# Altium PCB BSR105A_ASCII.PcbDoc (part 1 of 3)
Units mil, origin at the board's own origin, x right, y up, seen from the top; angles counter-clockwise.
Board outline 4010.03 x 4016.63 mil, 6 copper layers (Top Layer, Mid-Layer 1, Mid-Layer 2, Mid-Layer 3, Mid-Layer 4, Bottom Layer), stack 61.2 mil thick; 167 components, 58 nets, 398 pads, 190 vias.
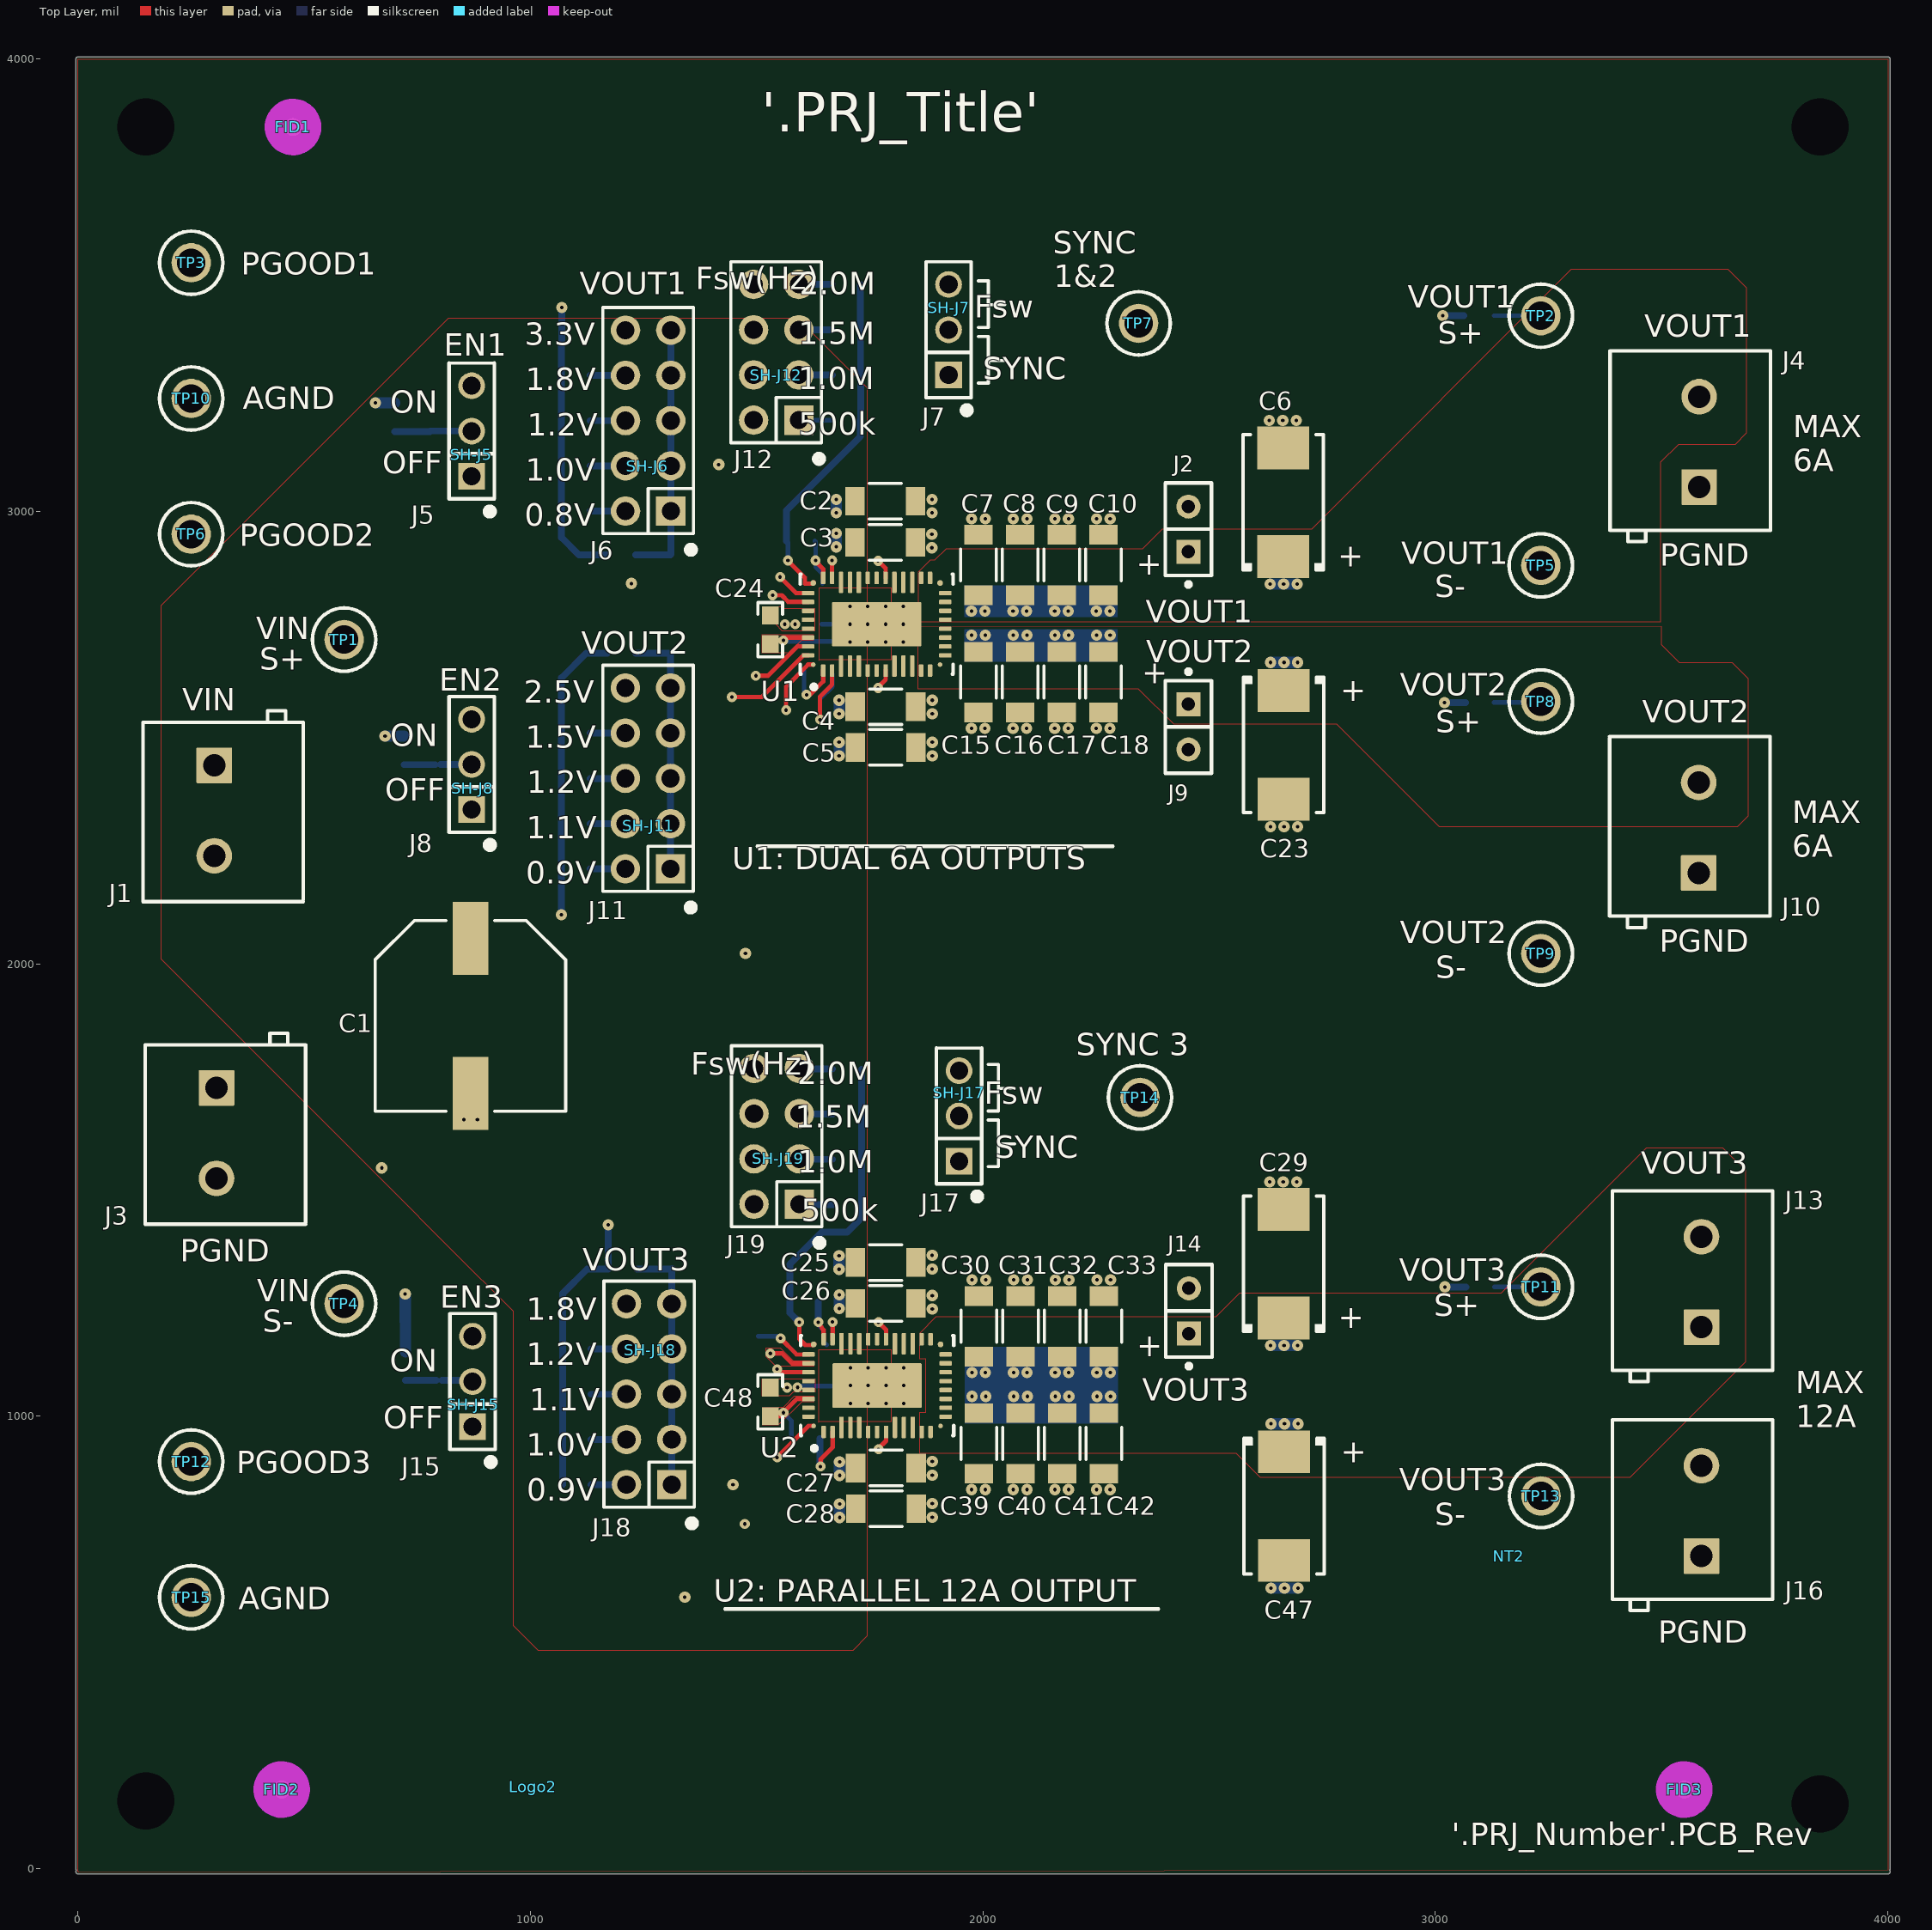
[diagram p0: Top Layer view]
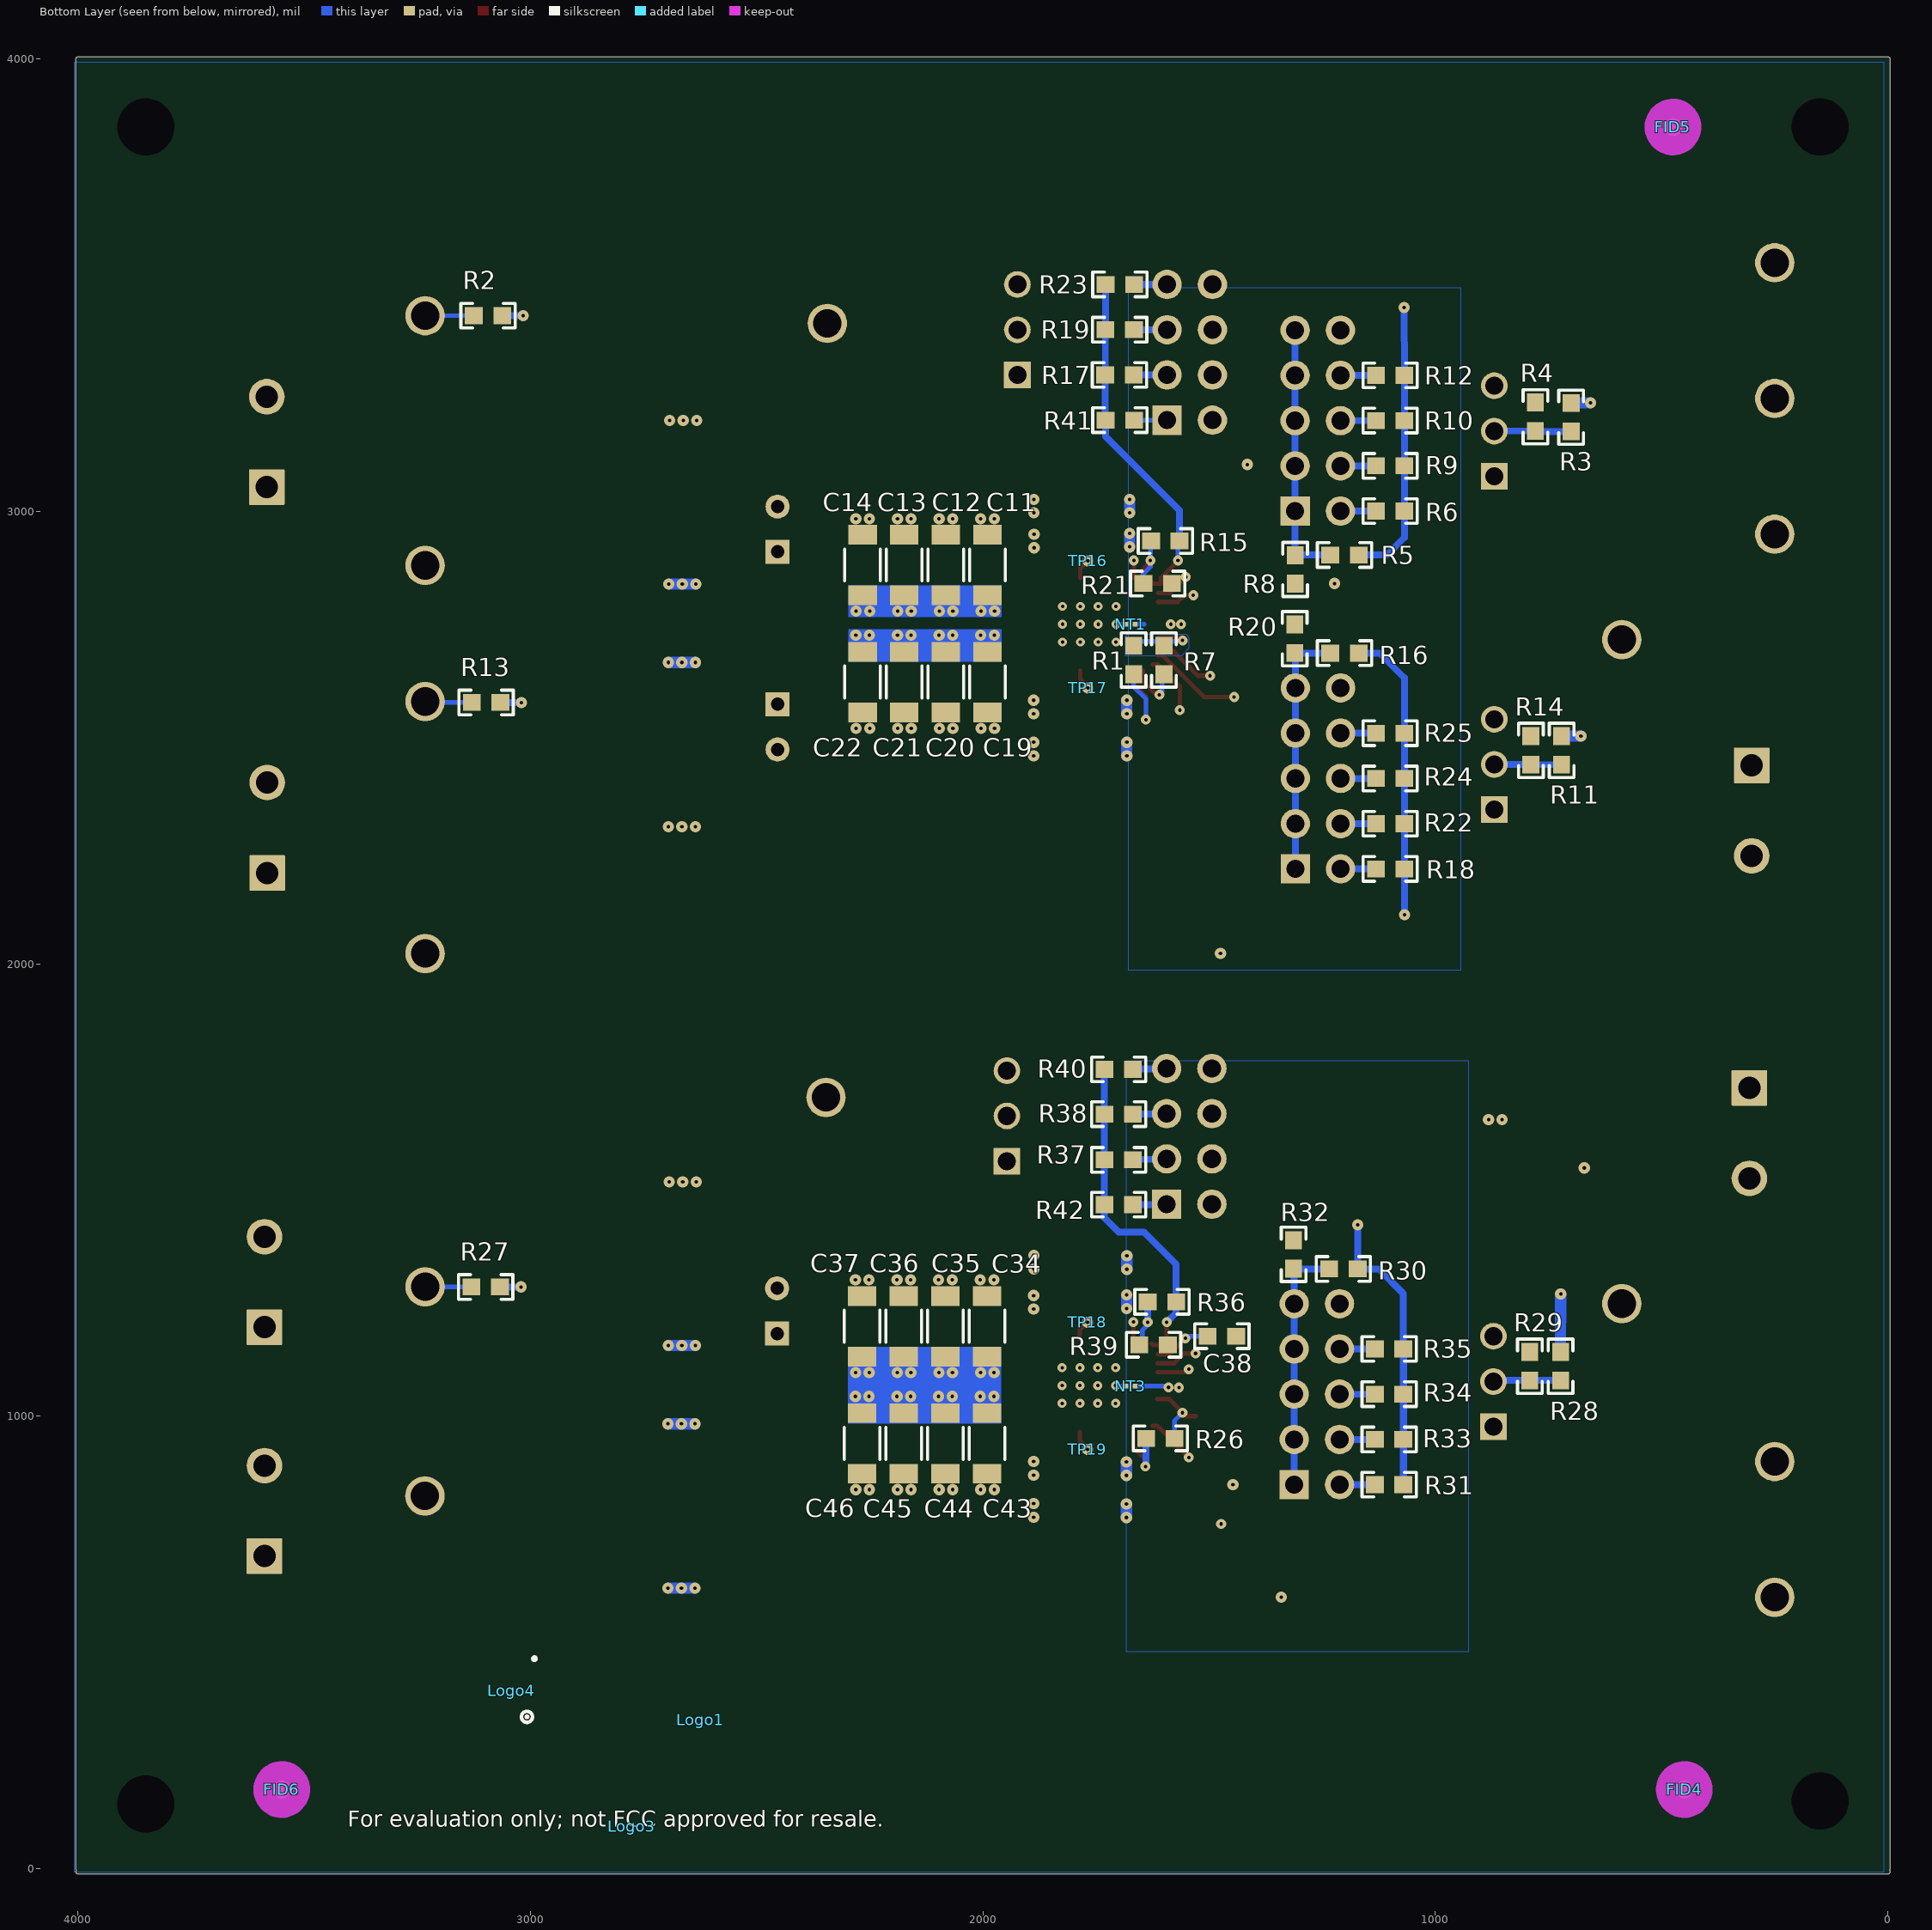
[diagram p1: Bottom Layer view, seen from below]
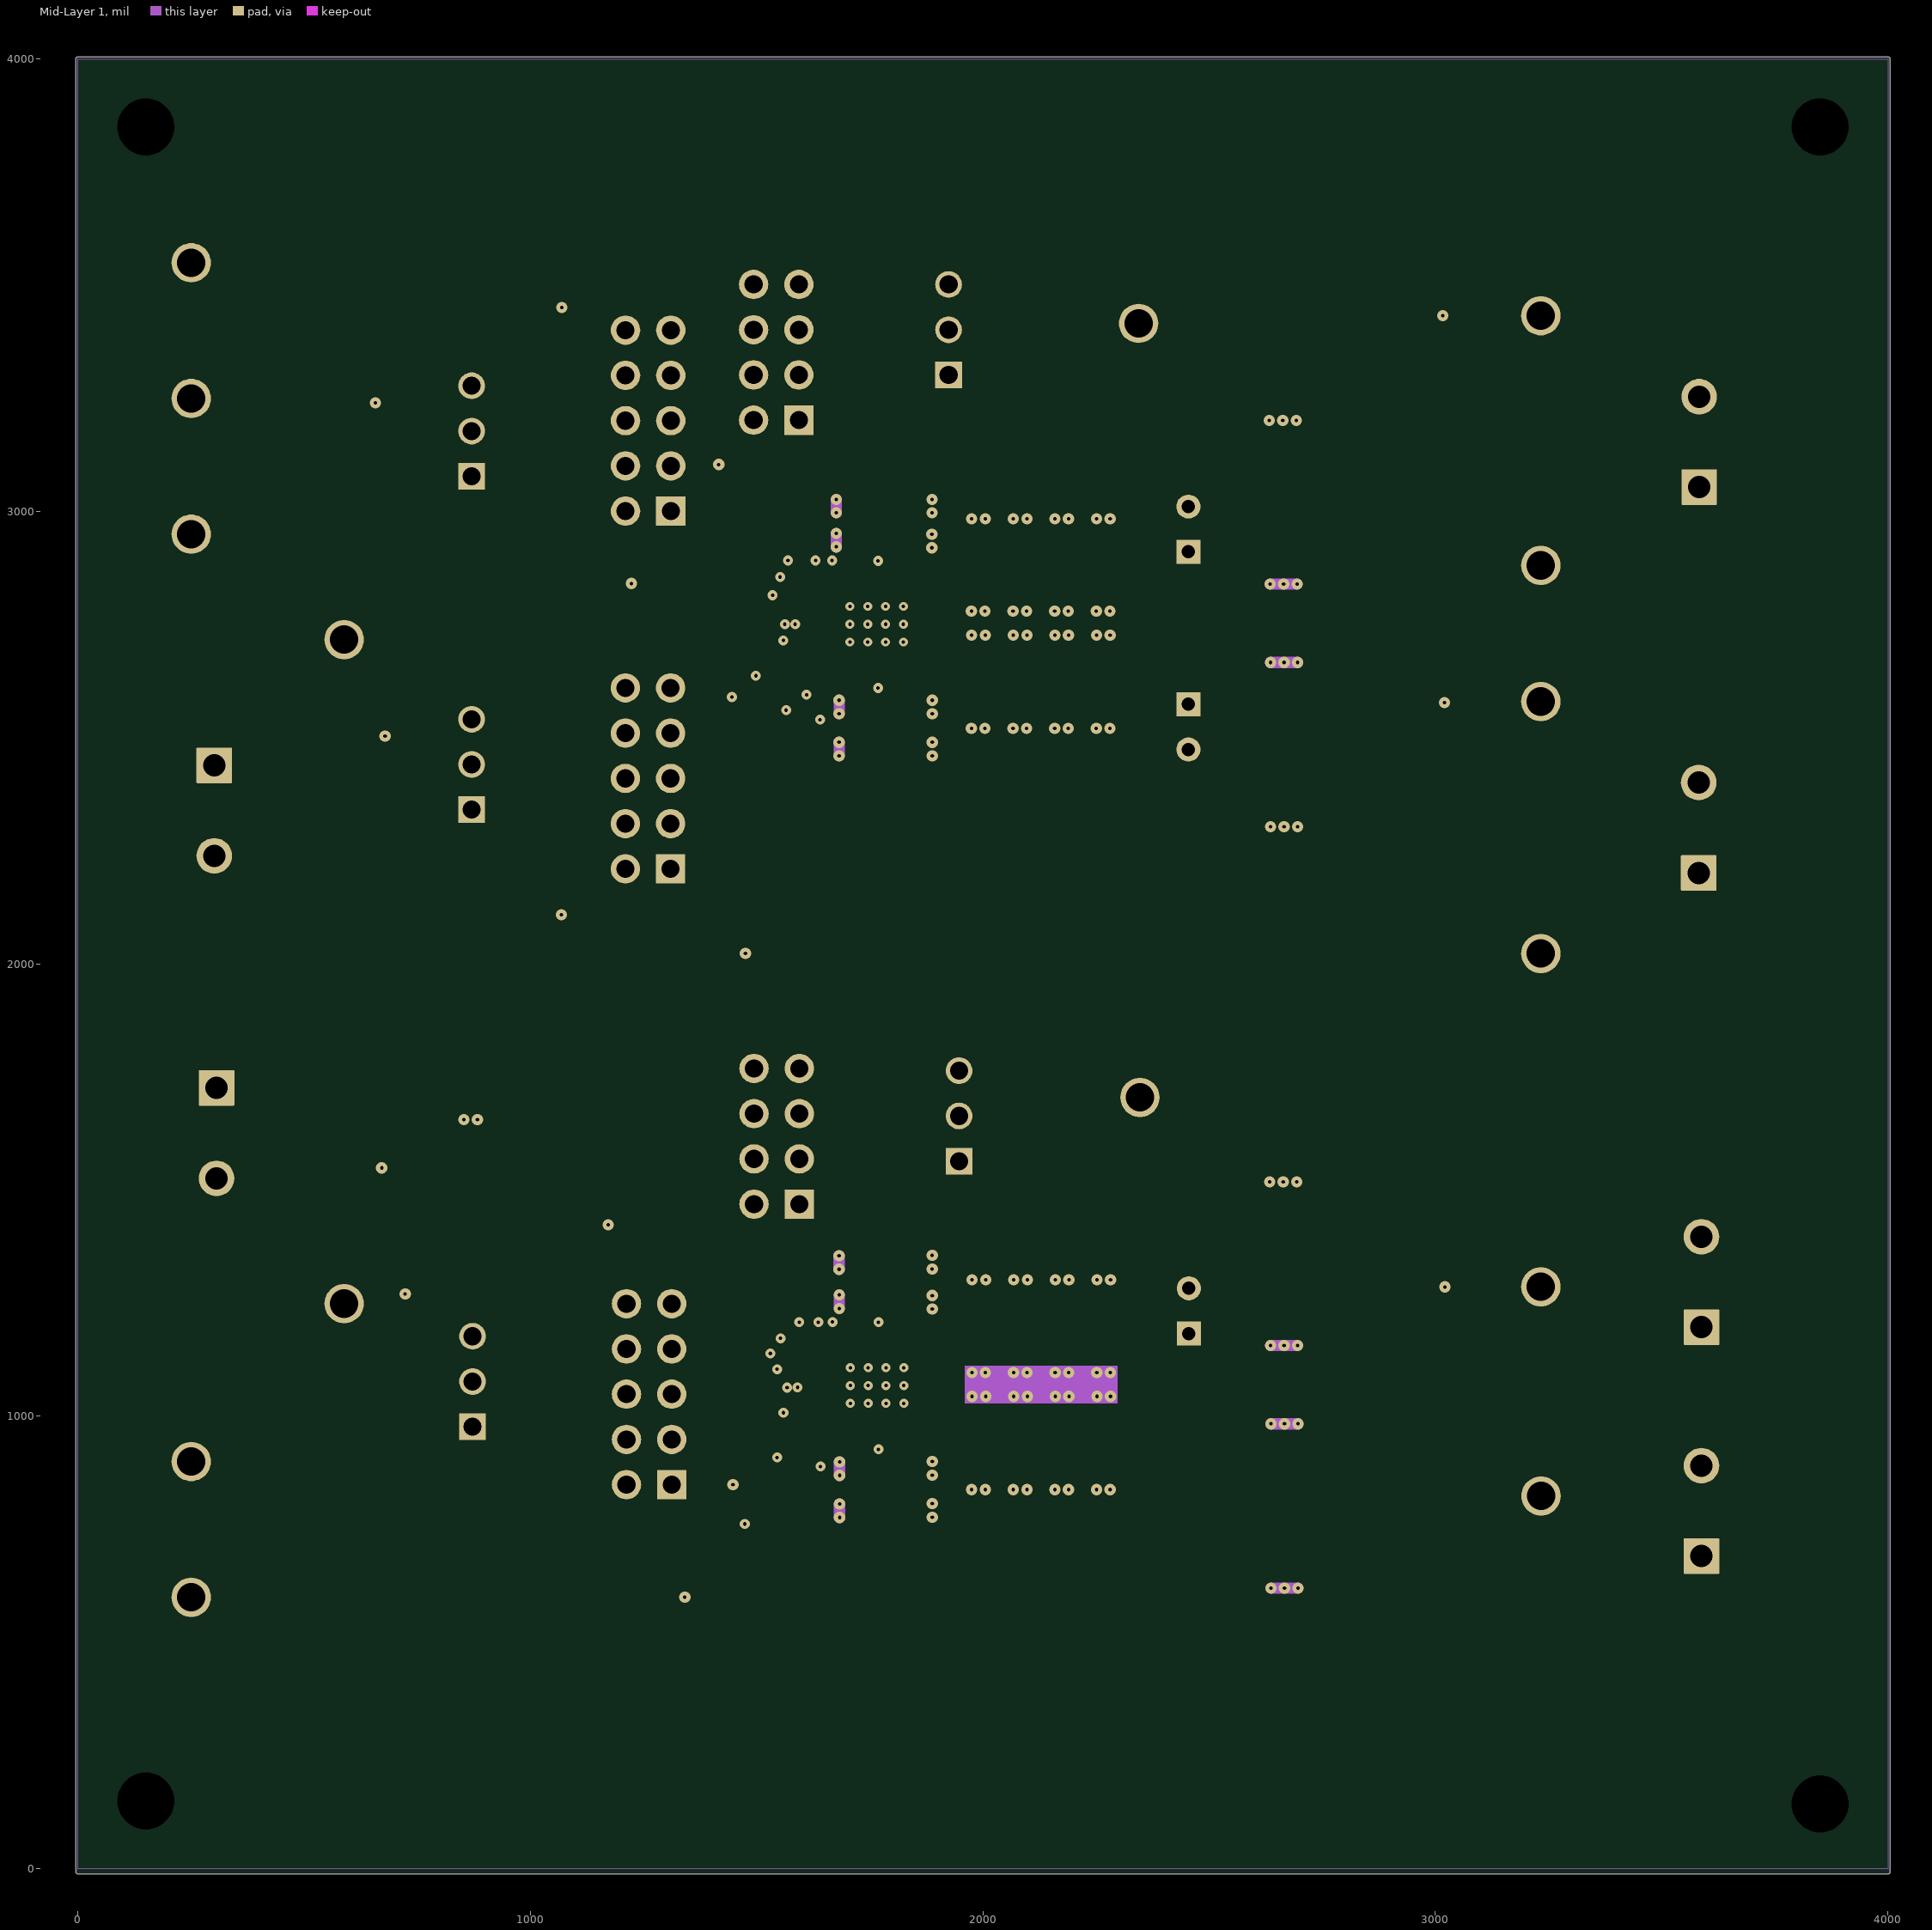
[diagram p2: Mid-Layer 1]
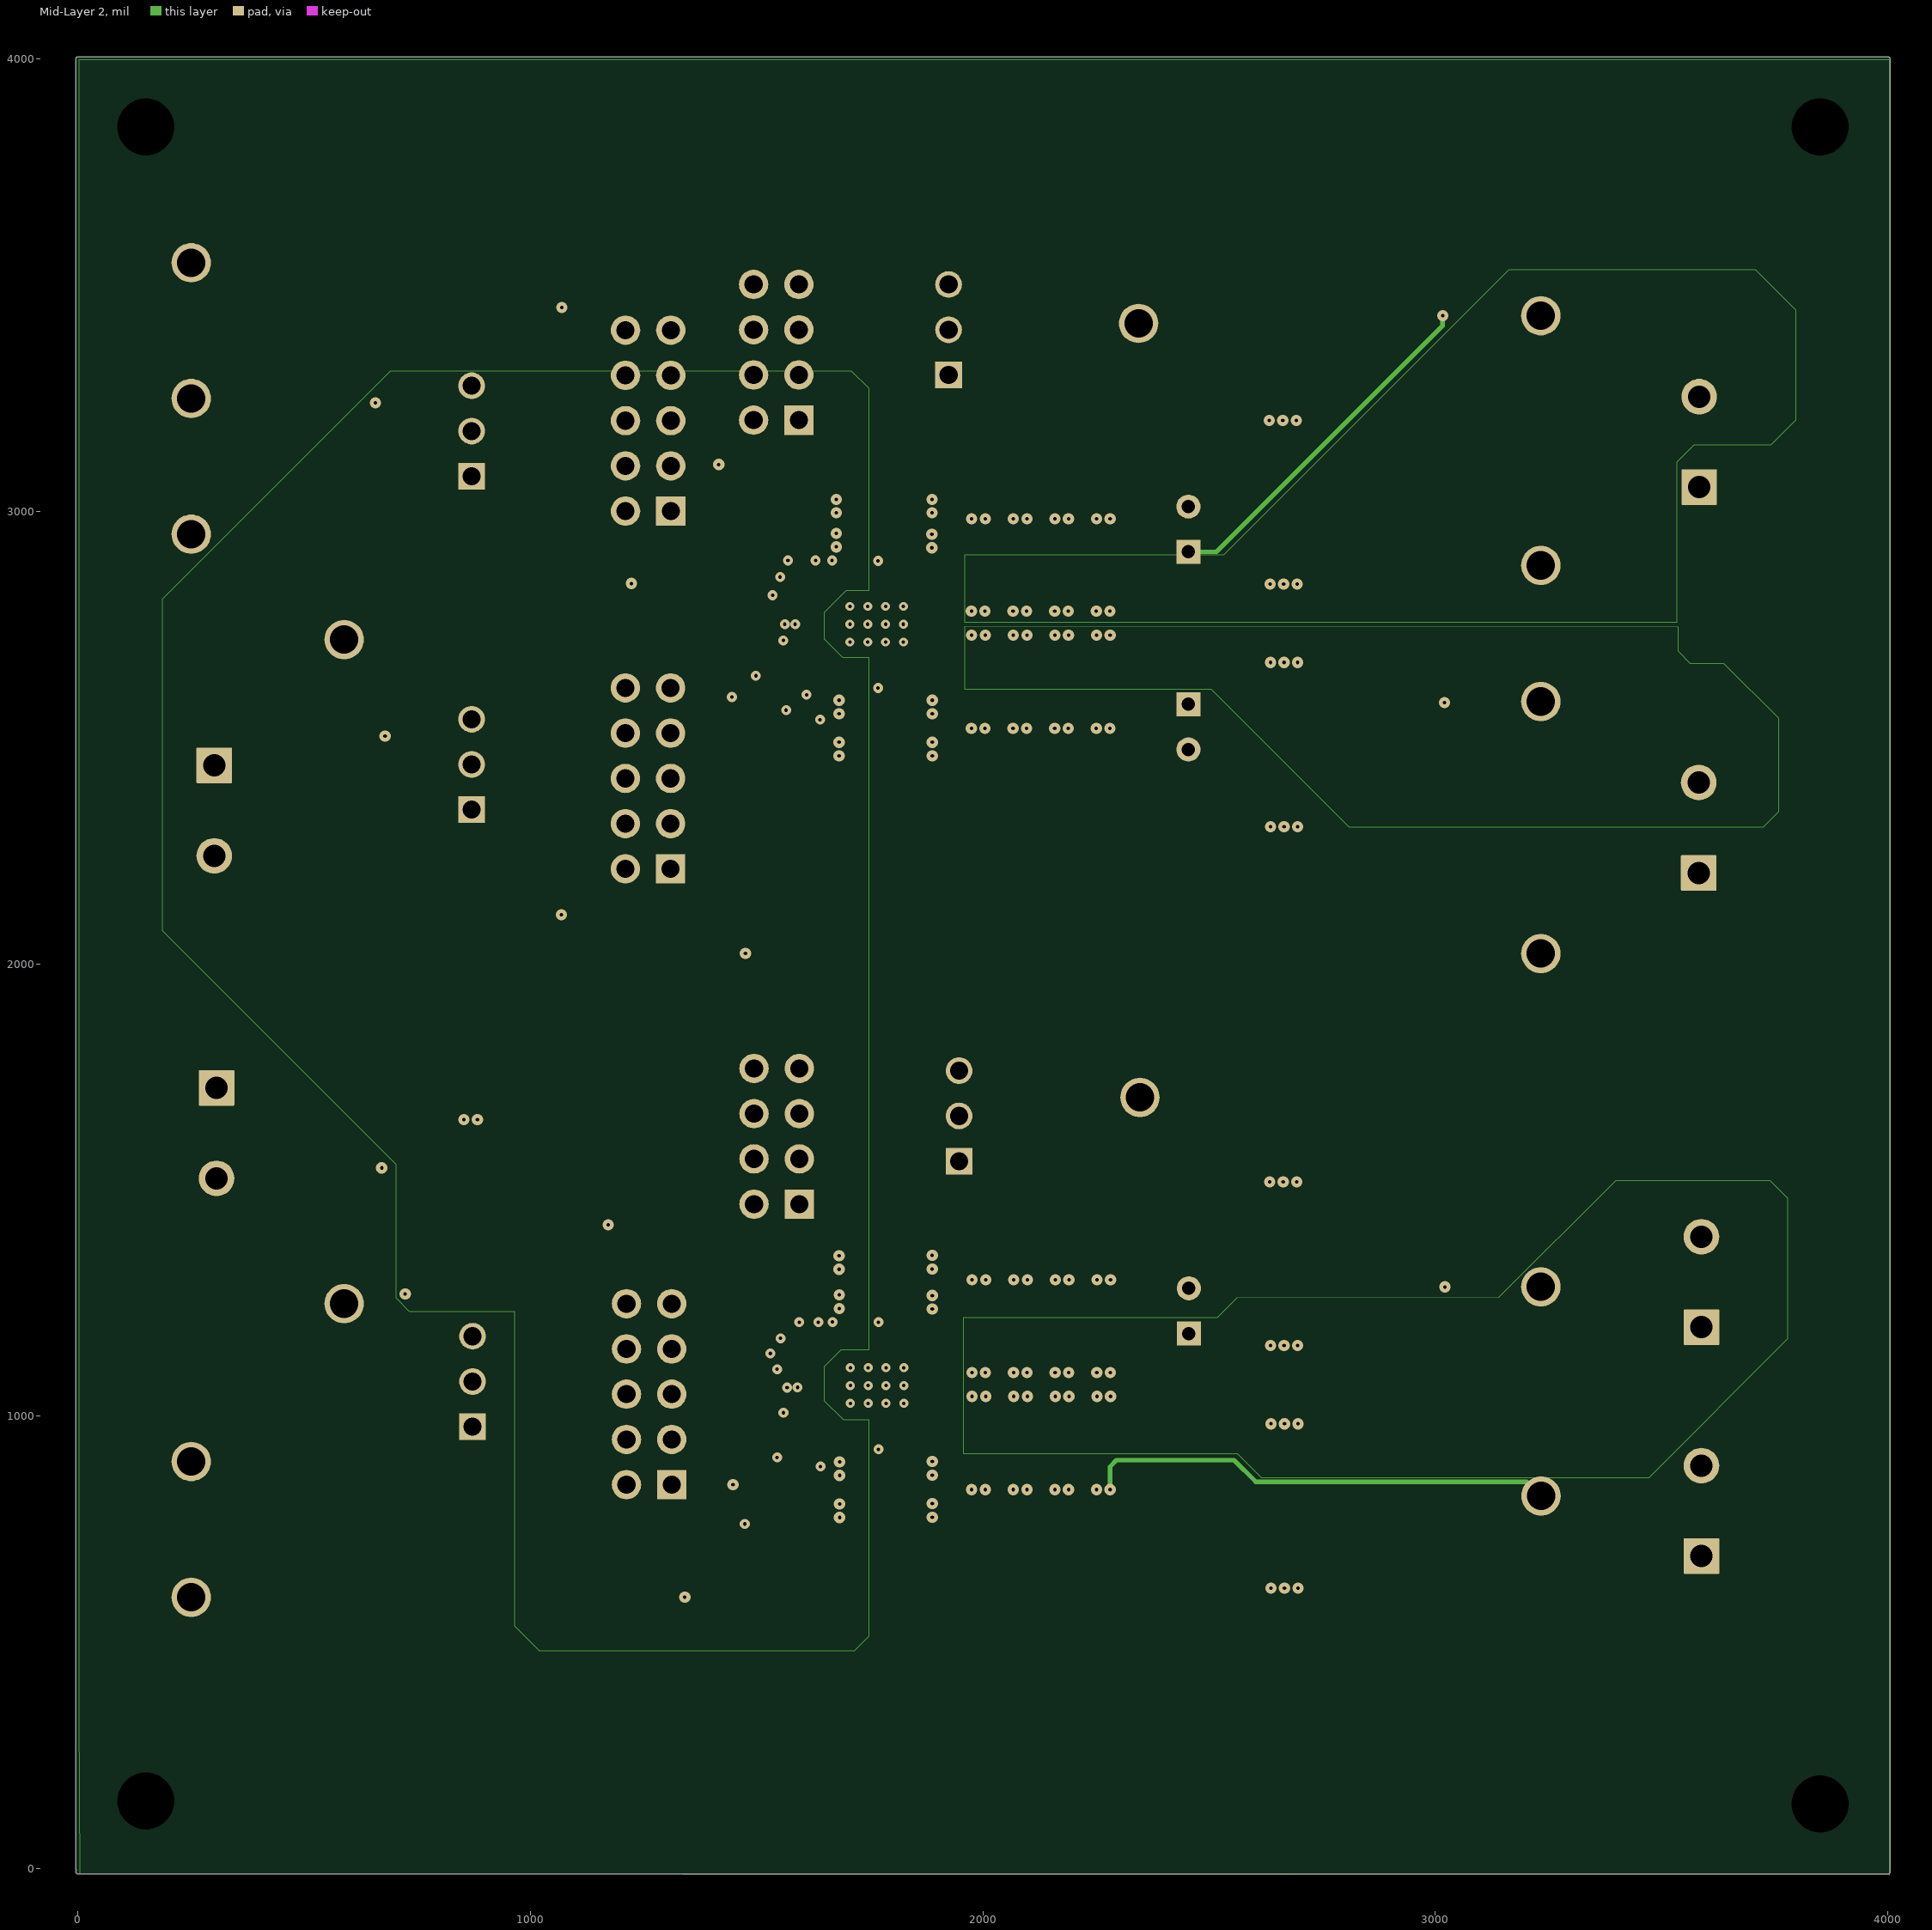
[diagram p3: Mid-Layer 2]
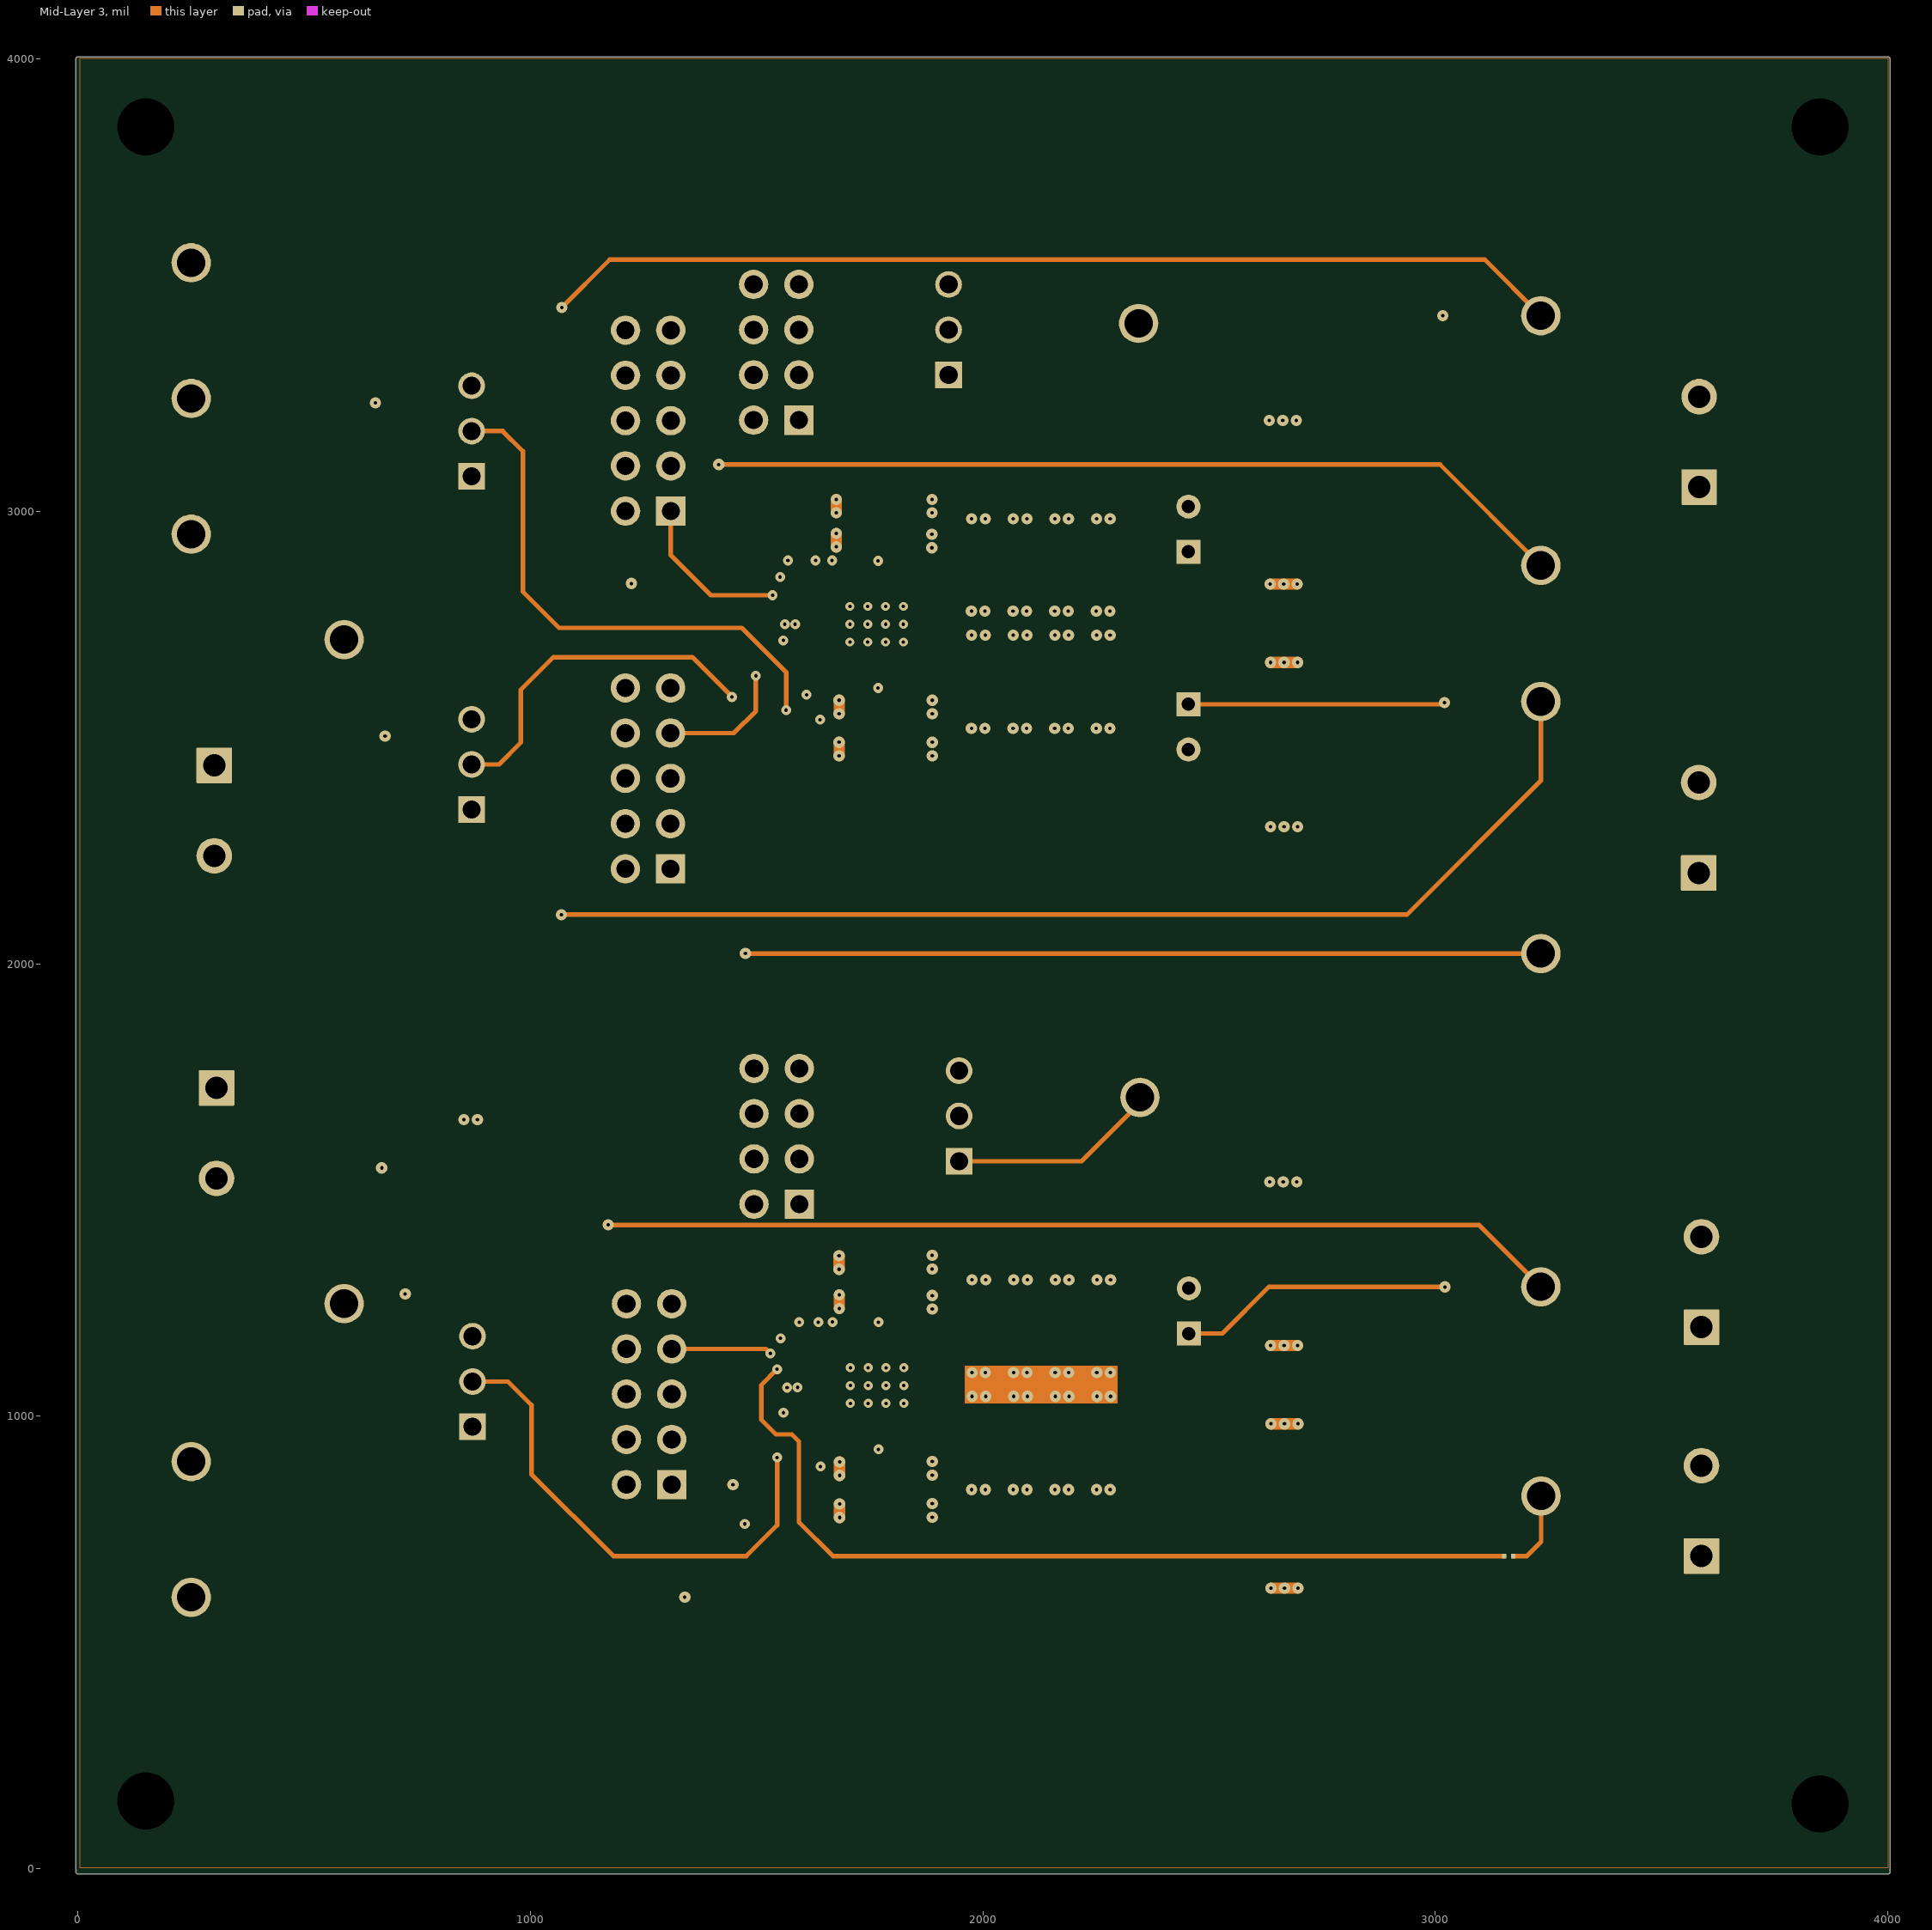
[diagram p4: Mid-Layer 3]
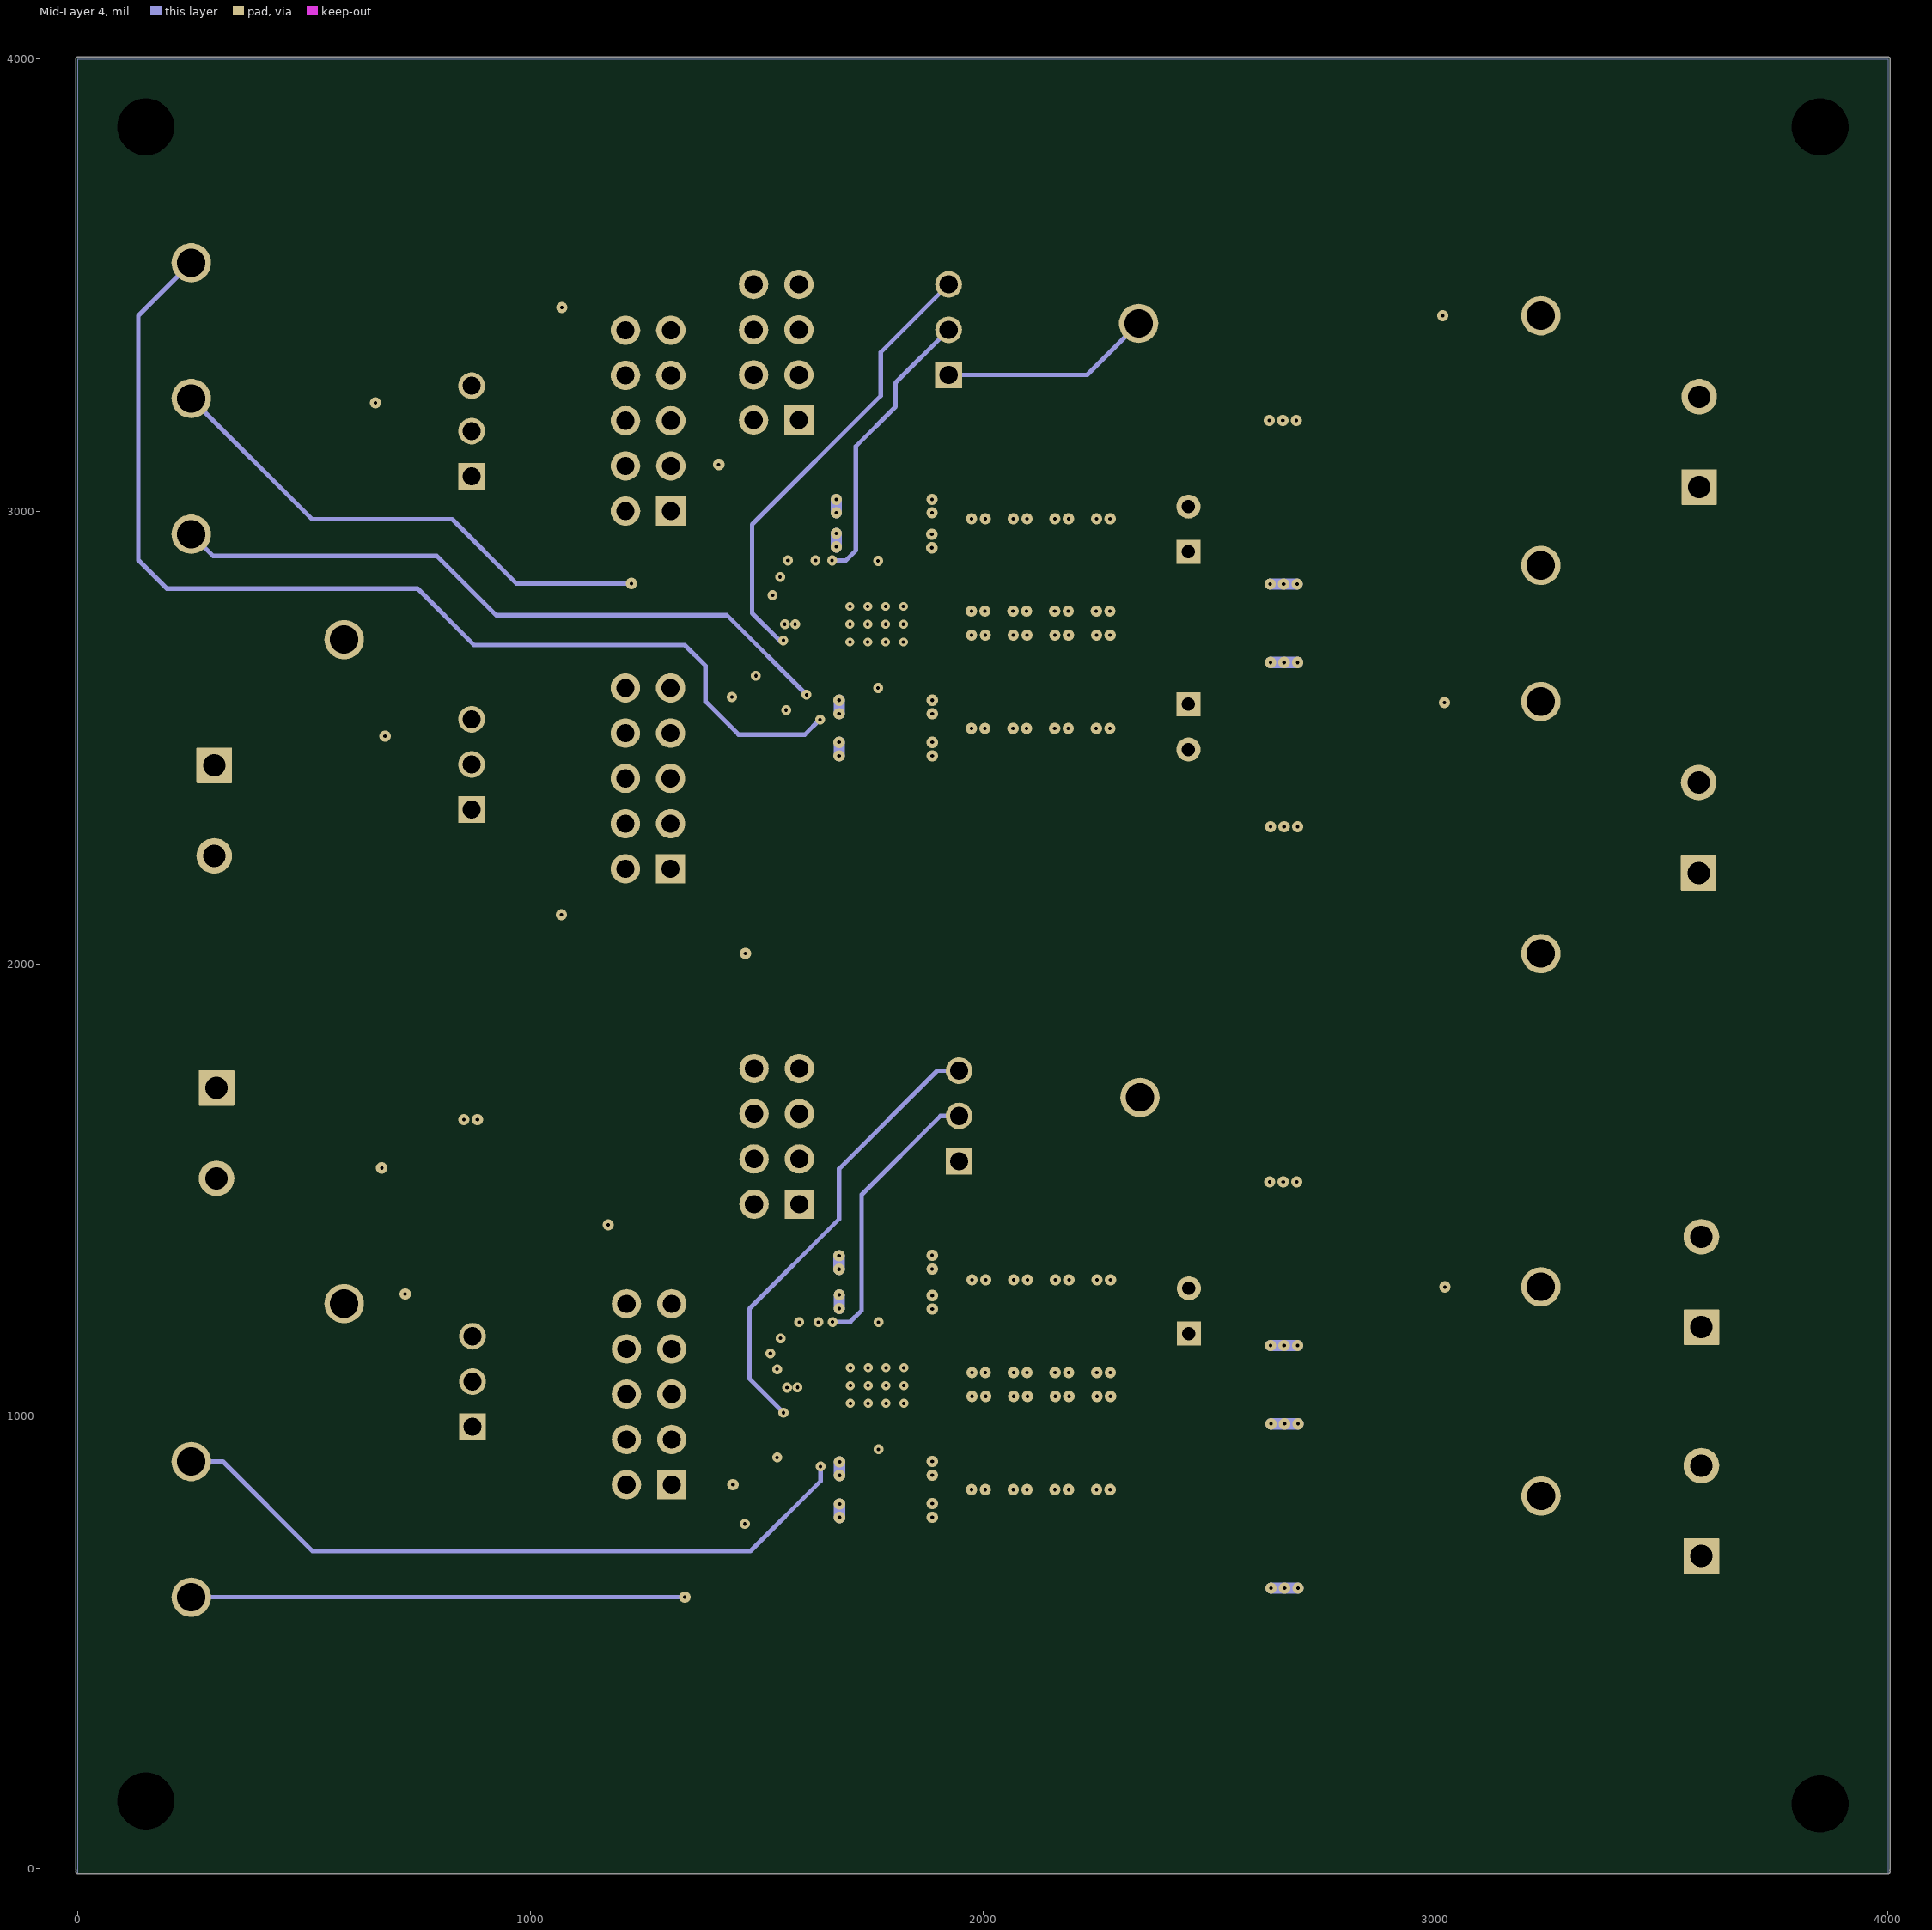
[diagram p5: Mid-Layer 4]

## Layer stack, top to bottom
Top Solder: solder mask 0.4, Solder Resist, Dk 3.5
Top Layer: signal copper 2
Dielectric1: prepreg 5, FR-4, Dk 4.2
Mid-Layer 1: signal copper 2.8
Dielectric2: core 12, FR-4, Dk 4.2
Mid-Layer 2: signal copper 2.8
Dielectric3: prepreg 12, FR-4, Dk 4.2
Mid-Layer 3: signal copper 2.8
Dielectric4: core 12, FR-4, Dk 4.2
Mid-Layer 4: signal copper 2.8
Dielectric5: prepreg 5, FR-4, Dk 4.2
Bottom Layer: signal copper 2
Bottom Solder: solder mask 0.4, Solder Resist, Dk 3.5

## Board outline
0,-11.61 cw(c0,-6.6) -3.78,-3.3 cw(c0,0) -5.01,0 -5.01,4000 cw(c0,4000) 0,4005.02 4000,4005.02 cw(c4000,4000) 4005.02,4000 4005.02,0 cw(c4000,0) 4003.78,-3.3 cw(c4000,-6.6) 4005.02,-6.6 cw(c4000,-6.6) 4000,-11.61

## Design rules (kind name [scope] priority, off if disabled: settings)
AcuteAngle [All] p0: scope1count=1 scope1_0_kind=Board scope1_0_value=Board scope2count=1 scope2_0_kind=Board scope2_0_value=Board commentlength=0 minimum=4.50000000000000E+0001
AcuteAngle [All] p1: minimum=4.50000000000000E+0001 checktracksonly=FALSE
AssemblyTestPointUsage [All] p0: scope1count=1 scope1_0_kind=Board scope1_0_value=Board scope2count=1 scope2_0_kind=Board scope2_0_value=Board commentlength=0
AssemblyTestPointUsage [All] p1: valid=2
AssemblyTestpoint [All] p0: scope1count=1 scope1_0_kind=Board scope1_0_value=Board scope2count=1 scope2_0_kind=Board scope2_0_value=Board commentlength=0
BoardOutlineClearance [All] p0 off: scope1count=1 scope1_0_kind=Board scope1_0_value=Board scope2count=1 scope2_0_kind=Board scope2_0_value=Board commentlength=173 gap=40 // Protel DXP Scope 1 Expression Was: OnCopper and not (InComponentClass('FiducialMark') or (Keepout or IsText) or  InComponentClass('Logo') or InRegion(1000,500,4000,800))
BoardOutlineClearance BoardOutlineClearance_Poly [All] p0 off: scope1count=1 scope1_0_kind=Board scope1_0_value=Board scope2count=1 scope2_0_kind=Board scope2_0_value=Board commentlength=58 gap=20 // Protel DXP Scope 1 Expression Was: OnCopper and InPoly
BoardOutlineClearance BoardOutlineClearance_MountingHoles [All] p0 off: scope1count=1 scope1_0_kind=Board scope1_0_value=Board scope2count=1 scope2_0_kind=Board scope2_0_value=Board commentlength=86 gap=40 // Protel DXP Scope 1 Expression Was: OnCopper and InComponentClass('Mounting Holes')
BoardOutlineClearance BoardOutlineClearance_MountingHoles [OnCopper and InComponentClass('Mounting Holes')] p1: gap=40 ignorepadtopadclearanceinfootprint=FALSE
BoardOutlineClearance BoardOutlineClearance_Poly [OnCopper and InPoly] p2: gap=20 ignorepadtopadclearanceinfootprint=FALSE
BoardOutlineClearance [OnCopper and not (InComponentClass('FiducialMark') or (Keepout or IsText) or  InComponentClass('Logo') or InRegion(1000,500,4000,800))] p3: gap=40 ignorepadtopadclearanceinfootprint=FALSE except(20: Poly-OutlineEdge)
Clearance Clearance_Poly [All] p0 off: scope1count=1 scope1_0_kind=Board scope1_0_value=Board scope2count=1 scope2_0_kind=Board scope2_0_value=Board commentlength=48 gap=9 // Protel DXP Scope 1 Expression Was: InPolygon
Clearance Clearance_U1-U2 [All] p0: scope1count=2 scope1_0_kind=Component scope1_0_value=U1 scope1_1_kind=Component scope1_1_value=U2 scope2count=1 scope2_0_kind=Board scope2_0_value=Board commentlength=0 gap=7
Clearance Clearance_BoardEdge [All] p0 off: scope1count=1 scope1_0_kind=Board scope1_0_value=Board scope2count=1 scope2_0_kind=Board scope2_0_value=Board commentlength=48 gap=22 // Protel DXP Scope 2 Expression Was: IsKeepOut
Clearance Clearance_BoardEdge_Poly [All] p0 off: scope1count=1 scope1_0_kind=Board scope1_0_value=Board scope2count=1 scope2_0_kind=Board scope2_0_value=Board commentlength=48 gap=25 // Protel DXP Scope 2 Expression Was: IsKeepOut
Clearance Clearance_BoardEdge_MountingHoles [All] p0 off: scope1count=1 scope1_0_kind=Board scope1_0_value=Board scope2count=1 scope2_0_kind=Board scope2_0_value=Board commentlength=48 gap=4 // Protel DXP Scope 2 Expression Was: IsKeepOut
Clearance "Clearance_Fiducial to Vout" [All] p0 off: scope1count=1 scope1_0_kind=ComponentClass scope1_0_value=FiducialMark scope2count=1 scope2_0_kind=Board scope2_0_value=Board commentlength=66 gap=20 // Protel DXP Scope 2 Expression Was: (IsTrack AND InNet('VOUT'))
Clearance "Clearance_Track and Keepout" [All] p0 off: scope1count=1 scope1_0_kind=Board scope1_0_value=Board scope2count=1 scope2_0_kind=Board scope2_0_value=Board commentlength=48 gap=20 // Protel DXP Scope 2 Expression Was: IsKeepOut
Clearance Clearance_U1-U2 [InComponent('U1') and InComponent('U2')] p1: gap=7 ignorepadtopadclearanceinfootprint=FALSE except(0: Arc-Hole Track-Hole SMDPad-Hole THPad-Hole Via-Hole Fill-Hole Poly-Hole Region-Hole Text-Hole; 5.9: SMDPad-SMDPad; 6: Arc-Fill Arc-Poly Arc-Region Track-Fill Track-Poly Track-Region SMDPad-Fill SMDPad-Poly SMDPad-Region Fill-Fill Fill-Poly Fill-Region Poly-Poly Poly-Region Region-Region)
Clearance Clearance_Poly [InPolygon] p2: gap=9 ignorepadtopadclearanceinfootprint=FALSE except(0: Arc-Hole Track-Hole SMDPad-Hole THPad-Hole Via-Hole Fill-Hole Poly-Hole Region-Hole Text-Hole)
Clearance "Clearance_Track and Keepout" [(IsTrack AND OnLayer('Top Layer') AND InNet('VOUT')) vs IsKeepOut] p3: gap=20 ignorepadtopadclearanceinfootprint=FALSE except(0: Arc-Hole Track-Hole SMDPad-Hole THPad-Hole Via-Hole Fill-Hole Poly-Hole Region-Hole Text-Hole)
Clearance "Clearance_Fiducial to Vout" [InComponentClass('FiducialMark') vs (IsTrack AND InNet('VOUT'))] p4: gap=20 ignorepadtopadclearanceinfootprint=FALSE except(0: Arc-Hole Track-Hole SMDPad-Hole THPad-Hole Via-Hole Fill-Hole Poly-Hole Region-Hole Text-Hole)
Clearance Clearance_BoardEdge_Poly [OnCopper and InPoly vs IsKeepOut] p5: gap=25 ignorepadtopadclearanceinfootprint=FALSE except(0: Arc-Hole Track-Hole SMDPad-Hole THPad-Hole Via-Hole Fill-Hole Poly-Hole Region-Hole Text-Hole)
Clearance Clearance_BoardEdge [OnCopper and Not InComponentClass('Logo') and not InComponentClass('FiducialMark') and not InRegion(1000,500,4000,800) and IsKeepOut vs IsKeepOut] p6: gap=22 ignorepadtopadclearanceinfootprint=FALSE except(0: Arc-Hole Track-Hole SMDPad-Hole THPad-Hole Via-Hole Fill-Hole Poly-Hole Region-Hole Text-Hole)
Clearance Clearance_BoardEdge_MountingHoles [OnCopper and InComponentClass('Mounting Holes') vs IsKeepOut] p7: gap=4 ignorepadtopadclearanceinfootprint=FALSE except(0: Arc-Hole Track-Hole SMDPad-Hole THPad-Hole Via-Hole Fill-Hole Poly-Hole Region-Hole Text-Hole)
ComponentClearance ComponentClearance_tp13 [All] p0: scope1count=1 scope1_0_kind=Component scope1_0_value=TP31 scope2count=1 scope2_0_kind=Component scope2_0_value=S31 commentlength=0 gap=24 collisioncheckmode=3
ComponentClearance ComponentClearance_Co37 [All] p0 off: scope1count=1 scope1_0_kind=Component scope1_0_value=Co37 scope2count=1 scope2_0_kind=Board scope2_0_value=Board commentlength=79 gap=0 collisioncheckmode=3 // Protel DXP Scope 2 Expression Was: InComponent('V31') or InComponent('V32')
ComponentClearance ComponentClearance_P12 [All] p0: scope1count=1 scope1_0_kind=Component scope1_0_value=P12 scope2count=1 scope2_0_kind=Component scope2_0_value=R18 commentlength=0 gap=0 collisioncheckmode=3
ComponentClearance ComponentClearance_P61 [All] p0 off: scope1count=1 scope1_0_kind=Component scope1_0_value=P61 scope2count=1 scope2_0_kind=Board scope2_0_value=Board commentlength=101 gap=0 collisioncheckmode=3 // Protel DXP Scope 2 Expression Was: InComponent('R62') or InComponent('J62') or InComponent('R61')
ComponentClearance ComponentClearance_S1 [All] p0: scope1count=1 scope1_0_kind=Component scope1_0_value=S1 scope2count=1 scope2_0_kind=Component scope2_0_value=TP15 commentlength=0 gap=0 collisioncheckmode=3
ComponentClearance ComponentClearance_R5 [All] p0 off: scope1count=1 scope1_0_kind=Component scope1_0_value=R5 scope2count=1 scope2_0_kind=Board scope2_0_value=Board commentlength=81 gap=0 collisioncheckmode=3 // Protel DXP Scope 2 Expression Was: InComponent('TP13') or InComponent('TP14')
ComponentClearance ComponentClearance_P2 [All] p0 off: scope1count=1 scope1_0_kind=Component scope1_0_value=P2 scope2count=1 scope2_0_kind=Board scope2_0_value=Board commentlength=77 gap=0 collisioncheckmode=3 // Protel DXP Scope 2 Expression Was: InComponent('C3') or InComponent('C4')
ComponentClearance ComponentClearance_P1 [All] p0 off: scope1count=1 scope1_0_kind=Component scope1_0_value=P1 scope2count=1 scope2_0_kind=Board scope2_0_value=Board commentlength=140 gap=0 collisioncheckmode=3 // Protel DXP Scope 2 Expression Was: InComponent('R1') or InComponent('R2') or InComponent('R3') or InComponent('R4') or InComponent('R5')
ComponentClearance ComponentClearance_R62 [All] p0 off: scope1count=1 scope1_0_kind=Component scope1_0_value=P62 scope2count=1 scope2_0_kind=Board scope2_0_value=Board commentlength=79 gap=0 collisioncheckmode=3 // Protel DXP Scope 2 Expression Was: InComponent('R63') or InComponent('R64')
ComponentClearance "ComponentClearance_P22 and R38" [All] p0: scope1count=1 scope1_0_kind=Component scope1_0_value=P22 scope2count=1 scope2_0_kind=Component scope2_0_value=R38 commentlength=0 gap=0 collisioncheckmode=3
ComponentClearance "ComponentClearance_P11 to Resistors" [All] p0 off: scope1count=1 scope1_0_kind=Component scope1_0_value=P11 scope2count=1 scope2_0_kind=Board scope2_0_value=Board commentlength=240 gap=0 collisioncheckmode=3 // Protel DXP Scope 2 Expression Was: InComponent('Rs11') or InComponent('Rs12') or InComponent('Rs13') or InComponent('Rs14') or InComponent('Rs15') or InComponent('R17') or InComponent('C14') or InComponent('NT32') or InComponent('NT12')
ComponentClearance "ComponentClearance_P21 to Resistors" [All] p0 off: scope1count=1 scope1_0_kind=Component scope1_0_value=P21 scope2count=1 scope2_0_kind=Board scope2_0_value=Board commentlength=217 gap=0 collisioncheckmode=3 // Protel DXP Scope 2 Expression Was: InComponent('Rs31') or InComponent('Rs32') or InComponent('Rs33') or InComponent('Rs34') or InComponent('Rs35') or InComponent('R37') or InComponent('C34') or InComponent('NT32')
ComponentClearance "ComponentClearance_Co17 adn V11" [All] p0: scope1count=1 scope1_0_kind=Component scope1_0_value=Co17 scope2count=1 scope2_0_kind=Component scope2_0_value=V11 commentlength=0 gap=0 collisioncheckmode=3
ComponentClearance [All] p0: scope1count=1 scope1_0_kind=Board scope1_0_value=Board scope2count=1 scope2_0_kind=Board scope2_0_value=Board commentlength=0 gap=20 collisioncheckmode=3
ComponentClearance ComponentClearance_THtoTH [All] p0 off: scope1count=1 scope1_0_kind=Board scope1_0_value=Board scope2count=1 scope2_0_kind=Board scope2_0_value=Board commentlength=54 gap=30 collisioncheckmode=3 // Protel DXP Scope 2 Expression Was: IsThruComponent
ComponentClearance ComponentClearance_THtoSMT [All] p0 off: scope1count=1 scope1_0_kind=Board scope1_0_value=Board scope2count=1 scope2_0_kind=Board scope2_0_value=Board commentlength=53 gap=10 collisioncheckmode=3 // Protel DXP Scope 2 Expression Was: IsSMTComponent
ComponentClearance ComponentClearance_SmallPassives [All] p0 off: scope1count=1 scope1_0_kind=Board scope1_0_value=Board scope2count=1 scope2_0_kind=Board scope2_0_value=Board commentlength=508 gap=14.96 collisioncheckmode=3 // Protel DXP Scope 2 Expression Was: HasFootprint('0201*') or HasFootprint('0402*') or HasFootprint('0508') or HasFootprint('0603*') or HasFootprint('0612') or HasFootprint('0805*') or HasFootprint('0815*') or HasFootprint('0830*') or HasFootprint('1206*') or HasFootprint('1210*') or HasFootprint('1808*') or HasFootprint('1812*') or HasFootprint('1825*') or HasFootprint('2010*') or HasFootprint('2220*') or HasFootprint('2225*') or HasFootprint('2512*') or HasFootprint('2728*') or HasFootprint('3518*')
ComponentClearance ComponentClearance_MountingHoles [All] p0: scope1count=1 scope1_0_kind=ComponentClass scope1_0_value="Mounting Holes" scope2count=1 scope2_0_kind=Board scope2_0_value=Board commentlength=0 gap=250 collisioncheckmode=3
ComponentClearance ComponentClearance_ScrewToNut [All] p0 off: scope1count=1 scope1_0_kind=Board scope1_0_value=Board scope2count=1 scope2_0_kind=Board scope2_0_value=Board commentlength=71 gap=5 collisioncheckmode=3 // Protel DXP Scope 2 Expression Was: (HasFootprint('Keystone_1902C'))
ComponentClearance ComponentClearance_Logo [All] p0: scope1count=1 scope1_0_kind=ComponentClass scope1_0_value=Logo scope2count=1 scope2_0_kind=Board scope2_0_value=Board commentlength=0 gap=25 collisioncheckmode=3
ComponentClearance ComponentClearance_Shunt [All] p0: scope1count=1 scope1_0_kind=ComponentClass scope1_0_value=Shunt scope2count=1 scope2_0_kind=Board scope2_0_value=Board commentlength=0 gap=0 collisioncheckmode=3
ComponentClearance ComponentClearance_MountingHoles_FiducialMarks [All] p0: scope1count=1 scope1_0_kind=ComponentClass scope1_0_value="Mounting Holes" scope2count=1 scope2_0_kind=ComponentClass scope2_0_value=FiducialMark commentlength=0 gap=50 collisioncheckmode=3
ComponentClearance ComponentClearance_S11 [All] p0 off: scope1count=1 scope1_0_kind=Component scope1_0_value=S11 scope2count=1 scope2_0_kind=Board scope2_0_value=Board commentlength=103 gap=0 collisioncheckmode=3 // Protel DXP Scope 2 Expression Was: InComponent('V11') or InComponent('Logo3') or InComponent('V12')
ComponentClearance ComponentClearance_S11 [InComponent('S11') vs InComponent('V11') or InComponent('Logo3') or InComponent('V12')] p1: gap=0 collisioncheckmode=3 verticalgap=0 showdistances=FALSE
ComponentClearance ComponentClearance_R62 [InComponent('P62') vs InComponent('R63') or InComponent('R64')] p2: gap=0 collisioncheckmode=3 verticalgap=0 showdistances=FALSE
ComponentClearance ComponentClearance_tp13 [InComponent('TP31') vs InComponent('S31')] p3: gap=24 collisioncheckmode=3 verticalgap=0 showdistances=FALSE
ComponentClearance ComponentClearance_P2 [InComponent('P2') vs InComponent('C3') or InComponent('C4')] p4: gap=0 collisioncheckmode=3 verticalgap=0 showdistances=FALSE
ComponentClearance ComponentClearance_Co37 [InComponent('Co37') vs InComponent('V31') or InComponent('V32')] p5: gap=0 collisioncheckmode=3 verticalgap=0 showdistances=FALSE
ComponentClearance ComponentClearance_P12 [InComponent('P12') vs InComponent('R18')] p6: gap=0 collisioncheckmode=3 verticalgap=0 showdistances=FALSE
ComponentClearance ComponentClearance_S1 [InComponent('S1') vs InComponent('TP15')] p7: gap=0 collisioncheckmode=3 verticalgap=0 showdistances=FALSE
ComponentClearance ComponentClearance_R5 [InComponent('R5') vs InComponent('TP13') or InComponent('TP14')] p8: gap=0 collisioncheckmode=3 verticalgap=0 showdistances=FALSE
ComponentClearance ComponentClearance_P61 [InComponent('P61') vs InComponent('R62') or InComponent('J62') or InComponent('R61')] p9: gap=0 collisioncheckmode=3 verticalgap=0 showdistances=FALSE
ComponentClearance ComponentClearance_P1 [InComponent('P1') vs InComponent('R1') or InComponent('R2') or InComponent('R3') or InComponent('R4') or InComponent('R5')] p10: gap=0 collisioncheckmode=3 verticalgap=0 showdistances=FALSE
ComponentClearance "ComponentClearance_P21 to Resistors" [InComponent('P21') vs InComponent('Rs31') or InComponent('Rs32') or InComponent('Rs33') or InComponent('Rs34') or InComponent('Rs35') or InComponent('R37') or InComponent('C34') or InComponent('NT32')] p11: gap=0 collisioncheckmode=3 verticalgap=0 showdistances=FALSE
ComponentClearance "ComponentClearance_P11 to Resistors" [InComponent('P11') vs InComponent('Rs11') or InComponent('Rs12') or InComponent('Rs13') or InComponent('Rs14') or InComponent('Rs15') or InComponent('R17') or InComponent('C14') or InComponent('NT32') or InComponent('NT12')] p12: gap=0 collisioncheckmode=3 verticalgap=0 showdistances=FALSE
ComponentClearance "ComponentClearance_Co17 adn V11" [InComponent('Co17') vs InComponent('V11')] p13: gap=0 collisioncheckmode=3 verticalgap=0 showdistances=FALSE
ComponentClearance "ComponentClearance_P22 and R38" [InComponent('P22') vs InComponent('R38')] p14: gap=0 collisioncheckmode=3 verticalgap=0 showdistances=FALSE
ComponentClearance ComponentClearance_MountingHoles_FiducialMarks [InComponentClass('Mounting Holes') vs InComponentClass('FiducialMark')] p15: gap=50 collisioncheckmode=3 verticalgap=10 showdistances=FALSE
ComponentClearance ComponentClearance_Shunt [InComponentClass('Shunt')] p16: gap=0 collisioncheckmode=3 verticalgap=0 showdistances=FALSE
ComponentClearance ComponentClearance_Logo [InComponentClass('Logo')] p17: gap=25 collisioncheckmode=3 verticalgap=10 showdistances=FALSE
ComponentClearance ComponentClearance_ScrewToNut [(HasFootprint('NY PMS 440 0025 PH')) vs (HasFootprint('Keystone_1902C'))] p18: gap=5 collisioncheckmode=3 verticalgap=10 showdistances=FALSE
ComponentClearance ComponentClearance_MountingHoles [InComponentClass('Mounting Holes')] p19: gap=250 collisioncheckmode=3 verticalgap=100000 showdistances=FALSE
ComponentClearance ComponentClearance_SmallPassives [HasFootprint('0201*') or HasFootprint('0402*') or HasFootprint('0508') or HasFootprint('0603*') or HasFootprint('0612') or HasFootprint('0805*') or HasFootprint('0815*') or HasFootprint('0830*') or HasFootprint('1206*') or HasFootprint('1210*') or HasFootprint('1808*') or HasFootprint('1812*') or HasFootprint('1825*') or HasFootprint('2010*') or HasFootprint('2220*') or HasFootprint('2225*') or HasFootprint('2512*') or HasFootprint('2728*') or HasFootprint('3518*') vs HasFootprint('0201*') or HasFootprint('0402*') or HasFootprint('0508') or HasFootprint('0603*') or HasFootprint('0612') or HasFootprint('0805*') or HasFootprint('0815*') or HasFootprint('0830*') or HasFootprint('1206*') or HasFootprint('1210*') or HasFootprint('1808*') or HasFootprint('1812*') or HasFootprint('1825*') or HasFootprint('2010*') or HasFootprint('2220*') or HasFootprint('2225*') or HasFootprint('2512*') or HasFootprint('2728*') or HasFootprint('3518*')] p20: gap=14.96 collisioncheckmode=3 verticalgap=10 showdistances=FALSE
ComponentClearance ComponentClearance_THtoSMT [IsThruComponent vs IsSMTComponent] p21: gap=10 collisioncheckmode=3 verticalgap=30 showdistances=FALSE
ComponentClearance ComponentClearance_THtoTH [IsThruComponent vs IsThruComponent] p22: gap=30 collisioncheckmode=3 verticalgap=30 showdistances=FALSE
ComponentClearance [All] p23: gap=20 collisioncheckmode=3 verticalgap=10 showdistances=FALSE
DiffPairsRouting [All] p0: scope1count=1 scope1_0_kind=Board scope1_0_value=Board scope2count=1 scope2_0_kind=Board scope2_0_value=Board commentlength=0
DiffPairsRouting [All] p1: maxlimit=100 minlimit=10 mostfreqgap=10 toplayer_minwidth=15 toplayer_maxwidth=15 toplayer_prefwidth=15 midlayer1_minwidth=15 midlayer1_maxwidth=15 midlayer1_prefwidth=15 midlayer2_minwidth=15 midlayer2_maxwidth=15 midlayer2_prefwidth=15 midlayer3_minwidth=15 midlayer3_maxwidth=15 midlayer3_prefwidth=15 midlayer4_minwidth=15 midlayer4_maxwidth=15 midlayer4_prefwidth=15 bottomlayer_minwidth=15 bottomlayer_maxwidth=15 bottomlayer_prefwidth=15 maxuncoupledlength=1000
FabricationTestPointUsage TestPointUsage [All] p0: scope1count=1 scope1_0_kind=Board scope1_0_value=Board scope2count=1 scope2_0_kind=Board scope2_0_value=Board commentlength=0 valid=2 allowmultiple=FALSE
FabricationTestPointUsage TestPointUsage [All] p1: valid=2 allowmultiple=FALSE
FabricationTestpoint Testpoint [All] p0: scope1count=1 scope1_0_kind=Board scope1_0_value=Board scope2count=1 scope2_0_kind=Board scope2_0_value=Board commentlength=0 side=3 testpointundercomponent=TRUE minsize=40 maxsize=100 preferedsize=60 minholesize=0 maxholesize=40 preferedholesize=32 testpointgrid=1
FabricationTestpoint Testpoint [All] p1: side=3 testpointundercomponent=TRUE minsize=40 maxsize=100 preferedsize=60 minholesize=0 maxholesize=40 preferedholesize=32 testpointgrid=1 allowsidetop=TRUE allowsidebottom=TRUE usegrid=TRUE gridtolerance=0.01
FanoutControl Fanout_Small [All] p0 off: scope1count=1 scope1_0_kind=Board scope1_0_value=Board scope2count=1 scope2_0_kind=Board scope2_0_value=Board commentlength=84 // Protel DXP Scope 1 Expression Was: (CompPinCount < 5)   Fanout_Small (Default Rule)
FanoutControl Fanout_Default [All] p0: scope1count=1 scope1_0_kind=Board scope1_0_value=Board scope2count=1 scope2_0_kind=Board scope2_0_value=Board commentlength=30 // Fanout_Default (Default Rule)
FanoutControl Fanout_SOIC [All] p0 off: scope1count=1 scope1_0_kind=Board scope1_0_value=Board scope2count=1 scope2_0_kind=Board scope2_0_value=Board commentlength=71 // Protel DXP Scope 1 Expression Was: IsSOIC   Fanout_SOIC (Default Rule)
FanoutControl Fanout_BGA [All] p0 off: scope1count=1 scope1_0_kind=Board scope1_0_value=Board scope2count=1 scope2_0_kind=Board scope2_0_value=Board commentlength=69 // Protel DXP Scope 1 Expression Was: IsBGA   Fanout_BGA (Default Rule)
FanoutControl Fanout_LCC [All] p0 off: scope1count=1 scope1_0_kind=Board scope1_0_value=Board scope2count=1 scope2_0_kind=Board scope2_0_value=Board commentlength=69 // Protel DXP Scope 1 Expression Was: IsLCC   Fanout_LCC (Default Rule)
FanoutControl Fanout_LCC [IsLCC] p1: bgadir=Out bgaviamode=Centered fanoutstyle=Auto fanoutdirection=Alternating viagrid=1 // Fanout_LCC (Default Rule)
FanoutControl Fanout_BGA [IsBGA] p2: bgadir=Out bgaviamode=Centered fanoutstyle=Auto fanoutdirection=Alternating viagrid=1 // Fanout_BGA (Default Rule)
FanoutControl Fanout_Default [All] p4: bgadir=Out bgaviamode=Centered fanoutstyle=Auto fanoutdirection=Alternating viagrid=1 // Fanout_Default (Default Rule)
FanoutControl Fanout_Small [(CompPinCount < 5)] p5: bgadir=Out bgaviamode=Centered fanoutstyle=Auto fanoutdirection=OutThenIn viagrid=1 // Fanout_Small (Default Rule)
Height [All] p0: scope1count=1 scope1_0_kind=Board scope1_0_value=Board scope2count=1 scope2_0_kind=Board scope2_0_value=Board commentlength=0
Height [All] p1: minheight=0 maxheight=1200 prefheight=500
HoleSize [All] p0: scope1count=1 scope1_0_kind=Board scope1_0_value=Board scope2count=1 scope2_0_kind=Board scope2_0_value=Board commentlength=0 absolutevalues=TRUE maxlimit=251 minlimit=7.87 maxpercent=80.000 minpercent=20.000
HoleSize HoleSize_BGA_Room [All] p0: scope1count=1 scope1_0_kind=Board scope1_0_value=Board scope2count=1 scope2_0_kind=Board scope2_0_value=Board commentlength=0 absolutevalues=TRUE maxlimit=130 minlimit=6 maxpercent=80.000 minpercent=20.000
HoleSize HoleSize_BGA_Room [All] p1: absolutevalues=TRUE maxlimit=130 minlimit=6 maxpercent=80.000 minpercent=20.000
HoleSize [All] p2: absolutevalues=TRUE maxlimit=251 minlimit=7.87 maxpercent=80.000 minpercent=20.000
HoleToHoleClearance [All] p0: scope1count=1 scope1_0_kind=Board scope1_0_value=Board scope2count=1 scope2_0_kind=Board scope2_0_value=Board commentlength=0
LayerPairs [All] p0: scope1count=1 scope1_0_kind=Board scope1_0_value=Board scope2count=1 scope2_0_kind=Board scope2_0_value=Board commentlength=0 enforce=TRUE
MinimumAnnularRing [All] p0: scope1count=1 scope1_0_kind=Board scope1_0_value=Board scope2count=1 scope2_0_kind=Board scope2_0_value=Board commentlength=0 minimumring=5.9
MinimumAnnularRing MinimumAnnularRing_ThermalPadVias [All] p0 off: scope1count=1 scope1_0_kind=Board scope1_0_value=Board scope2count=1 scope2_0_kind=Board scope2_0_value=Board commentlength=63 minimumring=5.91 // Protel DXP Scope 1 Expression Was: IsVia and InAnyComponent
MinimumAnnularRing MinimumAnnularRing_ThermalPadVias [IsVia and InAnyComponent] p1: minimumring=5.91
MinimumAnnularRing [All] p2: minimumring=5.9
MinimumSolderMaskSliver [All] p0: scope1count=1 scope1_0_kind=Board scope1_0_value=Board scope2count=1 scope2_0_kind=Board scope2_0_value=Board commentlength=0
MinimumSolderMaskSliver MinimumSolderMaskSliver_Logo [All] p0: scope1count=1 scope1_0_kind=ComponentClass scope1_0_value=Logo scope2count=1 scope2_0_kind=ComponentClass scope2_0_value=Logo commentlength=0
MinimumSolderMaskSliver MinimumSolderMaskSliver_Logo [InComponentClass('Logo') vs InComponentClass('Logo')] p1: minsoldermaskwidth=0.7
MinimumSolderMaskSliver [All] p2: minsoldermaskwidth=2.95
NetAntennae [All] p0 off: scope1count=1 scope1_0_kind=Board scope1_0_value=Board scope2count=1 scope2_0_kind=Board scope2_0_value=Board commentlength=46 // Protel DXP Scope 1 Expression Was: IsTrack
NetAntennae [IsTrack] p1: netantennaetolerance=0
PasteMaskExpansion [All] p0: scope1count=1 scope1_0_kind=Board scope1_0_value=Board scope2count=1 scope2_0_kind=Board scope2_0_value=Board commentlength=0 expansion=0
PlaneClearance [All] p0: scope1count=1 scope1_0_kind=Board scope1_0_value=Board scope2count=1 scope2_0_kind=Board scope2_0_value=Board commentlength=0 clearance=20
PlaneConnect [All] p0: scope1count=1 scope1_0_kind=Board scope1_0_value=Board scope2count=1 scope2_0_kind=Board scope2_0_value=Board commentlength=0 planeconnectstyle=Relief reliefexpansion=10 reliefentries=4 reliefconductorwidth=10 reliefairgap=10
PlaneConnect [All] p1: planeconnectstyle=Relief reliefexpansion=10 reliefentries=4 reliefconductorwidth=10 reliefairgap=10
PolygonConnect [All] p0: scope1count=1 scope1_0_kind=Board scope1_0_value=Board scope2count=1 scope2_0_kind=Board scope2_0_value=Board commentlength=0 connectstyle=Direct reliefconductorwidth=10 reliefentries=4 polygonreliefangle="90 Angle"
PolygonConnect PolygonConnect_Isthrupin [All] p0 off: scope1count=1 scope1_0_kind=Board scope1_0_value=Board scope2count=1 scope2_0_kind=Board scope2_0_value=Board commentlength=48 connectstyle=Relief reliefconductorwidth=25 reliefentries=4 polygonreliefangle="90 Angle" // Protel DXP Scope 1 Expression Was: IsThruPin
PolygonConnect PolygonConnect_Isthrupin [IsThruPin] p1: connectstyle=Relief reliefconductorwidth=25 reliefentries=4 polygonreliefangle="90 Angle" airgapwidth=10
PolygonConnect [All] p2: connectstyle=Direct reliefconductorwidth=10 reliefentries=4 polygonreliefangle="90 Angle" airgapwidth=10
RoutingCorners [All] p0: scope1count=1 scope1_0_kind=Board scope1_0_value=Board scope2count=1 scope2_0_kind=Board scope2_0_value=Board commentlength=0 cornerstyle=45-Degree minsetback=100 maxsetback=100
RoutingLayers [All] p0: scope1count=1 scope1_0_kind=Board scope1_0_value=Board scope2count=1 scope2_0_kind=Board scope2_0_value=Board commentlength=0 top layer=Automatic mid layer 1=Automatic mid layer 2=Automatic mid layer 3=Automatic mid layer 4=Automatic bottom layer=Automatic
RoutingPriority [All] p0: scope1count=1 scope1_0_kind=Board scope1_0_value=Board scope2count=1 scope2_0_kind=Board scope2_0_value=Board commentlength=0
RoutingTopology [All] p0: scope1count=1 scope1_0_kind=Board scope1_0_value=Board scope2count=1 scope2_0_kind=Board scope2_0_value=Board commentlength=0 topology=Shortest
RoutingVias [All] p0: scope1count=1 scope1_0_kind=Board scope1_0_value=Board scope2count=1 scope2_0_kind=Board scope2_0_value=Board commentlength=0 holewidth=16 width=34 viastyle="Through Hole" minholewidth=7.87 minwidth=24 maxholewidth=40 maxwidth=65
RoutingVias ThermalPadVias [All] p0 off: scope1count=1 scope1_0_kind=Board scope1_0_value=Board scope2count=1 scope2_0_kind=Board scope2_0_value=Board commentlength=63 holewidth=7.87 width=19.68 viastyle="Through Hole" minholewidth=7.87 minwidth=19.68 maxholewidth=12.99 maxwidth=23.62 // Protel DXP Scope 1 Expression Was: IsVia and InAnyComponent
RoutingVias RoutingVias_BGA_Room [All] p0: scope1count=1 scope1_0_kind=Board scope1_0_value=Board scope2count=1 scope2_0_kind=Board scope2_0_value=Board commentlength=0 holewidth=28 width=50 viastyle="Through Hole" minholewidth=6 minwidth=18 maxholewidth=28 maxwidth=50
RoutingVias RoutingVias_BGA_Room [All] p1: holewidth=28 width=50 viastyle="Through Hole" minholewidth=6 minwidth=18 maxholewidth=28 maxwidth=50
RoutingVias ThermalPadVias [IsVia and InAnyComponent] p2: holewidth=7.87 width=19.68 viastyle="Through Hole" minholewidth=7.87 minwidth=19.68 maxholewidth=12.99 maxwidth=23.62
RoutingVias [All] p3: holewidth=16 width=34 viastyle="Through Hole" minholewidth=7.87 minwidth=24 maxholewidth=40 maxwidth=65
ShortCircuit [All] p0: scope1count=1 scope1_0_kind=Board scope1_0_value=Board scope2count=1 scope2_0_kind=Board scope2_0_value=Board commentlength=0 allowed=FALSE
ShortCircuit ShortCircuit_1 [All] p0 off: scope1count=1 scope1_0_kind=Net scope1_0_value=AGND scope2count=1 scope2_0_kind=Net scope2_0_value=PGND commentlength=0 allowed=TRUE
ShortCircuit ShortCircuit_1 [InNet('AGND') vs InNet('PGND')] p1 off: allowed=TRUE
ShortCircuit [All] p2: allowed=FALSE
SilkToBoardRegionClearance [All] p0 off: scope1count=1 scope1_0_kind=Board scope1_0_value=Board scope2count=1 scope2_0_kind=Board scope2_0_value=Board commentlength=130 // Protel DXP Scope 1 Expression Was: Not ((IsComment or IsDesignator) And (Hide <> 'False')) and not InRegion(1000,500,4000,800)
SilkToBoardRegionClearance [Not ((IsComment or IsDesignator) And (Hide <> 'False')) and not InRegion(1000,500,4000,800)] p1:
SilkToSilkClearance [All] p0: scope1count=1 scope1_0_kind=Board scope1_0_value=Board scope2count=1 scope2_0_kind=Board scope2_0_value=Board commentlength=0
SilkToSilkClearance SilkToSilkClearance_Pb-FreeLogo [All] p0 off: scope1count=1 scope1_0_kind=Board scope1_0_value=Board scope2count=1 scope2_0_kind=Board scope2_0_value=Board commentlength=120 // Protel DXP Scope 2 Expression Was: (HasFootprint('Pb-Free_Overlay_Medium') OR HasFootprint('Pb-Free_Overlay_Small'))
SilkToSilkClearance SilkToSilkClearance_Pb-FreeLogo [(HasFootprint('Pb-Free_Overlay_Medium') OR HasFootprint('Pb-Free_Overlay_Small')) vs (HasFootprint('Pb-Free_Overlay_Medium') OR HasFootprint('Pb-Free_Overlay_Small'))] p1: silktosilkclearance=0
SilkToSilkClearance [All] p2: silktosilkclearance=4
SilkToSolderMaskClearance SilkToComponentPadClearance [All] p0 off: scope1count=1 scope1_0_kind=Board scope1_0_value=Board scope2count=1 scope2_0_kind=Board scope2_0_value=Board commentlength=63 // Protel DXP Scope 1 Expression Was: IsPad and InAnycomponent
SilkToSolderMaskClearance SilkToComponentPadClearance [IsPad and InAnycomponent] p1: minsilkscreentomaskgap=3 clearancetoexposedcopper=TRUE
SolderMaskExpansion [All] p0: scope1count=1 scope1_0_kind=Board scope1_0_value=Board scope2count=1 scope2_0_kind=Board scope2_0_value=Board commentlength=0 expansion=1.97
SolderMaskExpansion SolderMaskExpansion_Via [All] p0 off: scope1count=1 scope1_0_kind=Board scope1_0_value=Board scope2count=1 scope2_0_kind=Board scope2_0_value=Board commentlength=44 expansion=0 // Protel DXP Scope 1 Expression Was: Isvia
SolderMaskExpansion SolderMaskExpansion_Via [Isvia] p1: expansion=0
SolderMaskExpansion [All] p2: expansion=1.97
UnRoutedNet [All] p0: scope1count=1 scope1_0_kind=Board scope1_0_value=Board scope2count=1 scope2_0_kind=Board scope2_0_value=Board commentlength=0
UnpouredPolygon [All] p0: scope1count=1 scope1_0_kind=Board scope1_0_value=Board scope2count=1 scope2_0_kind=Board scope2_0_value=Board commentlength=0
Width [All] p0: scope1count=1 scope1_0_kind=Board scope1_0_value=Board scope2count=1 scope2_0_kind=Board scope2_0_value=Board commentlength=0 maxlimit=100 minlimit=8 preferedwidth=10
Width [All] p1: maxlimit=100 minlimit=8 preferedwidth=10 checkconnectedcopper=TRUE
12 further rules are at their usual default settings.

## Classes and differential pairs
component class Shunt: SH-J5 SH-J6 SH-J7 SH-J8 SH-J11 SH-J12 SH-J15 SH-J17 SH-J18 SH-J19
component class BSR105A_SHT1: C1 C2 C3 C4 C5 C6 C7 C8 C9 C10 C11 C12 C13 C14 C15 C16 C17 C18 C19 C20 C21 C22 C23 C24 Co37 J1 J2 J3 J4 J5 J6 J7 J8 J9 J10 J11 J12 J25 M31 M42 NT1 R1 R2 R3 R4 R5 R6 R7 R8 R9 R10 R11 R12 R13 R14 R15 R16 R17 R18 R19 R20 R21 R22 R23 R24 R25 R41 TP1 TP2 TP3 TP4 TP5 TP6 TP7 TP8 TP9 TP10 TP16 TP17 U1 V31
component class BSR105A_SHT2: C25 C26 C27 C28 C29 C30 C31 C32 C33 C34 C35 C36 C37 C38 C39 C40 C41 C42 C43 C44 C45 C46 C47 C48 Ci13 Co16 Co18 D11 D12 J13 J14 J15 J16 J17 J18 J19 M22 NT2 NT3 P11 P13 R26 R27 R28 R29 R30 R31 R32 R33 R34 R35 R36 R37 R38 R39 R40 R42 R52 Ri0 S3 S12 S22 TP11 TP12 TP13 TP14 TP15 TP18 TP19 TP64 TP67 TP68 U2
component class Header: J5 J6 J7 J8 J11 J12 J15 J17 J18 J19 J53 J54 J61 J62 J63 J64 J65 M23 M31 P54
component class Logo: Logo2
component class BSR105A_Hardware: FID1 FID2 FID3 FID4 FID5 FID6 Logo1 Logo2 Logo3 Logo4 SH-J5 SH-J6 SH-J7 SH-J8 SH-J11 SH-J12 SH-J15 SH-J17 SH-J18 SH-J19 ZZ1 ZZ2 ZZ3 ZZ4 ZZ5 ZZ6 ZZ7 ZZ8 ZZ9 ZZ10 ZZ11 ZZ12 ZZ13 ZZ14
component class FiducialMark: FID1 FID2 FID3 FID4 FID5 FID6
component class AssemblyNote: ZZ1 ZZ2 ZZ3 ZZ4 ZZ5 ZZ6 ZZ7 ZZ8 ZZ9 ZZ10 ZZ11 ZZ12 ZZ13 ZZ14

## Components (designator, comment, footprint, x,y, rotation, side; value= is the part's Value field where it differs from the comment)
C1 "EEE-FC1E331P" SM_RADIAL_G 867,1885 r270 top
C2 "C3216X5R1E476M160AC" 1206_190 1784,3023 r0 top
C3 "C3216X5R1E476M160AC" 1206_190 1784,2932 r0 top
C4 "C3216X5R1E476M160AC" 1206_190 1784.65,2568.64 r0 top
C5 "C3216X5R1E476M160AC" 1206_190 1784.82,2478.55 r0 top
C6 "T520Y337M010ATE035" 7343-40 2663.5,3020.41 r90 top
C7 "GRM31CR60J107ME39L" 1206_180 1990,2882 r90 top
C8 "GRM31CR60J107ME39L" 1206_180 2082,2882 r90 top
C9 "GRM31CR60J107ME39L" 1206_180 2174,2882 r90 top
C10 "GRM31CR60J107ME39L" 1206_180 2266,2882 r90 top
C11 "GRM31CR60J107ME39L" 1206_180 1990,2882 r90 bottom
C12 "GRM31CR60J107ME39L" 1206_180 2082,2882 r90 bottom
C13 "GRM31CR60J107ME39L" 1206_180 2174,2882 r90 bottom
C14 "GRM31CR60J107ME39L" 1206_180 2266,2882 r90 bottom
C15 "GRM31CR60J107ME39L" 1206_180 1990,2623 r270 top
C16 "GRM31CR60J107ME39L" 1206_180 2082,2623 r270 top
C17 "GRM31CR60J107ME39L" 1206_180 2174,2623 r270 top
C18 "GRM31CR60J107ME39L" 1206_180 2266,2623 r270 top
C19 "GRM31CR60J107ME39L" 1206_180 1990,2623 r270 bottom
C20 "GRM31CR60J107ME39L" 1206_180 2082,2623 r270 bottom
C21 "GRM31CR60J107ME39L" 1206_180 2174,2623 r270 bottom
C22 "GRM31CR60J107ME39L" 1206_180 2266,2623 r270 bottom
C23 "T520Y337M010ATE035" 7343-40 2664.5,2484.41 r270 top
C24 "C1608X6S1C225K080AC" 0603 1530,2739 r90 top
C25 "C3216X5R1E476M160AC" 1206_190 1784.82,1340.08 r0 top
C26 "C3216X5R1E476M160AC" 1206_190 1785,1249.66 r0 top
C27 "C3216X5R1E476M160AC" 1206_190 1785.65,885.64 r0 top
C28 "C3216X5R1E476M160AC" 1206_190 1785.82,795.55 r0 top
C29 "T520Y337M010ATE035" 7343-40 2664.5,1337.41 r90 top
C30 "GRM31CR60J107ME39L" 1206_180 1991,1199 r90 top
C31 "GRM31CR60J107ME39L" 1206_180 2083,1199 r90 top
C32 "GRM31CR60J107ME39L" 1206_180 2175,1199 r90 top
C33 "GRM31CR60J107ME39L" 1206_180 2267,1199 r90 top
C34 "GRM31CR60J107ME39L" 1206_180 1991,1199 r90 bottom
C35 "GRM31CR60J107ME39L" 1206_180 2083,1199 r90 bottom
C36 "GRM31CR60J107ME39L" 1206_180 2175,1199 r90 bottom
C37 "GRM31CR60J107ME39L" 1206_180 2267,1199 r90 bottom
C38 "C1608X7R1H473K080AA" 0603 1472,1177 r180 bottom
C39 "GRM31CR60J107ME39L" 1206_180 1991,940 r270 top
C40 "GRM31CR60J107ME39L" 1206_180 2083,940 r270 top
C41 "GRM31CR60J107ME39L" 1206_180 2175,940 r270 top
C42 "GRM31CR60J107ME39L" 1206_180 2267,940 r270 top
C43 "GRM31CR60J107ME39L" 1206_180 1991,940 r270 bottom
C44 "GRM31CR60J107ME39L" 1206_180 2083,940 r270 bottom
C45 "GRM31CR60J107ME39L" 1206_180 2175,940 r270 bottom
C46 "GRM31CR60J107ME39L" 1206_180 2267,940 r270 bottom
C47 "T520Y337M010ATE035" 7343-40 2665.5,801.41 r270 top
C48 "C1608X6S1C225K080AC" 0603 1530,1032 r90 top
FID1 "Fiducial" Fiducial10-30 475,3850 r0 top
FID2 "Fiducial" Fiducial10-30 450,175 r0 top
FID3 "Fiducial" Fiducial10-30 3550,175 r0 top
FID4 "Fiducial" Fiducial10-30 450,175 r180 bottom
FID5 "Fiducial" Fiducial10-30 475,3850 r180 bottom
FID6 "Fiducial" Fiducial10-30 3550,175 r180 bottom
J1 "ED120/2DS" On-Shore_ED120_2DS 301,2339 r270 top
J2 "310-43-102-41-001000" Mill-max_310-43-102-41-001000 2454,2961 r90 top
J3 "ED120/2DS" On-Shore_ED120_2DS 306,1626 r270 top
J4 "ED120/2DS" On-Shore_ED120_2DS 3583,3154 r90 top
J5 "PEC03SAAN" CONN_PEC03SAAN 870,3178 r90 top
J6 "PEC05DAAN" CONN_PEC05DAAN 1260,3201 r90 top
J7 "PEC03SAAN" CONN_PEC03SAAN 1924,3402 r90 top
J8 "PEC03SAAN" CONN_PEC03SAAN 870,2441 r90 top
J9 "310-43-102-41-001000" Mill-max_310-43-102-41-001000 2454,2524 r270 top
J10 "ED120/2DS" On-Shore_ED120_2DS 3582,2301 r90 top
J11 "PEC05DAAN" CONN_PEC05DAAN 1259.59,2410.17 r90 top
J12 "PEC04DAAN" CONN_PEC04DAAN 1543,3352 r90 top
J13 "ED120/2DS" On-Shore_ED120_2DS 3588,1297 r90 top
J14 "310-43-102-41-001000" Mill-max_310-43-102-41-001000 2455,1233 r90 top
J15 "PEC03SAAN" CONN_PEC03SAAN 872,1077 r90 top
J16 "ED120/2DS" On-Shore_ED120_2DS 3588,791 r90 top
J17 "PEC03SAAN" CONN_PEC03SAAN 1947,1664 r90 top
J18 "PEC05DAAN" CONN_PEC05DAAN 1262,1049 r90 top
J19 "PEC04DAAN" CONN_PEC04DAAN 1544,1619 r90 top
Logo1 "CE Mark" CE_Mark_5mm 2625,329 r180 bottom
Logo2 "Texas Instruments" TI_Stacked_Overlay_Small 1005,181 r0 top
Logo3 "FCC disclaimer" FCC_disclaimer 2777,94 r180 bottom
Logo4 "WEEE logo" WEEE_Minimum 3042,394 r180 bottom
NT1 "Net-Tie" Net-Tie_10mil#1 1674,2751 r0 bottom net-tie
NT2 "Net-Tie" Net-Tie_10mil#2 3162,691 r0 top net-tie
NT3 "Net-Tie" Net-Tie_10mil#1 1674,1067 r0 bottom net-tie
R1 "CRCW060310K0FKEA" 0603 1667,2672 r90 bottom
R2 "CRCW06030000Z0EA" 0603 3094,3433 r180 bottom
R3 "CRCW0603100KFKEA" 0603 700,3208.59 r90 bottom
R4 "CRCW060334K8FKEA" 0603 779,3209.59 r270 bottom
R5 "CRCW060356K2FKEA" 0603 1201,2904 r180 bottom
R6 "CRCW06036K81FKEA" 0603 1100,3001 r180 bottom
R7 "CRCW060310K0FKEA" 0603 1600,2672 r90 bottom
R8 "CRCW060310K0FKEA" 0603 1310,2872 r90 bottom
R9 "CRCW060312K1FKEA" 0603 1100,3101 r180 bottom
R10 "CRCW060318K7FKEA" 0603 1100,3201 r180 bottom
R11 "CRCW0603100KFKEA" 0603 721,2472 r90 bottom
R12 "CRCW060348K7FKEA" 0603 1100,3301 r180 bottom
R13 "CRCW06030000Z0EA" 0603 3098,2578 r180 bottom
R14 "CRCW060334K8FKEA" 0603 789,2472 r270 bottom
R15 "CRCW060310K0FKEA" 0603 1597,2935 r0 bottom
R16 "CRCW060340K2FKEA" 0603 1201,2687 r180 bottom
R17 "CRCW060317K4FKEA" 0603 1698.5,3302 r0 bottom
R18 "CRCW060310K0FKEA" 0603 1100,2210 r180 bottom
R19 "CRCW060328K7FKEA" 0603 1698,3402 r0 bottom
R20 "CRCW060310K0FKEA" 0603 1311,2719 r270 bottom
R21 "CRCW060315K4FKEA" 0603 1614,2841 r0 bottom
R22 "CRCW060317K4FKEA" 0603 1100,2310 r180 bottom
R23 "CRCW060353K6FKEA" 0603 1697.5,3502 r0 bottom
R24 "CRCW060321K5FKEA" 0603 1100,2410 r180 bottom
R25 "CRCW060340K2FKEA" 0603 1100,2510 r180 bottom
R26 "CRCW060310K0FKEA" 0603 1608,951 r180 bottom
R27 "CRCW06030000Z0EA" 0603 3099,1286 r180 bottom
R28 "CRCW0603100KFKEA" 0603 723.41,1110.83 r90 bottom
R29 "CRCW060334K8FKEA" 0603 791.41,1110.83 r270 bottom
R30 "CRCW060326K1FKEA" 0603 1203.41,1325.83 r180 bottom
R31 "CRCW060311K5FKEA" 0603 1102.41,848.83 r180 bottom
R32 "CRCW060310K0FKEA" 0603 1313.41,1357.83 r270 bottom
R33 "CRCW060316K2FKEA" 0603 1102.41,948.83 r180 bottom
R34 "CRCW060322K1FKEA" 0603 1102.41,1048.83 r180 bottom
R35 "CRCW060330K1FKEA" 0603 1102.41,1148.83 r180 bottom
R36 "CRCW060310K0FKEA" 0603 1604.5,1253 r0 bottom
R37 "CRCW060317K4FKEA" 0603 1700,1567 r0 bottom
R38 "CRCW060328K7FKEA" 0603 1700,1668 r0 bottom
R39 "CRCW060310K7FKEA" 0603 1623,1158 r0 bottom
R40 "CRCW060353K6FKEA" 0603 1700,1767 r0 bottom
R41 "CRCW060310K7FKEA" 0603 1697.5,3202 r0 bottom
R42 "CRCW060310K7FKEA" 0603 1700,1468 r0 bottom
SH-J5 "2SN-BK-G" 2SN-BK-G 869,3126 r270 top
SH-J6 "2SN-BK-G" 2SN-BK-G 1259,3100 r180 top
SH-J7 "2SN-BK-G" 2SN-BK-G 1925,3451 r90 top
SH-J8 "2SN-BK-G" 2SN-BK-G 872,2388 r90 top
SH-J11 "2SN-BK-G" 2SN-BK-G 1260,2306 r180 top
SH-J12 "2SN-BK-G" 2SN-BK-G 1542,3302 r180 top
SH-J15 "2SN-BK-G" 2SN-BK-G 873,1026 r90 top
SH-J17 "2SN-BK-G" 2SN-BK-G 1947,1715 r90 top
SH-J18 "2SN-BK-G" 2SN-BK-G 1264,1147 r180 top
SH-J19 "2SN-BK-G" 2SN-BK-G 1547,1570 r180 top
TP1 "5010" Keystone5010 588,2717 r180 top
TP2 "5010" Keystone5010 3233,3433 r0 top
TP3 "5012" Keystone5012 250,3550 r180 top
TP4 "5011" Keystone5011 588,1249 r0 top
TP5 "5011" Keystone5011 3233,2881 r0 top
TP6 "5012" Keystone5012 250,2950 r0 top
TP7 "5012" Keystone5012 2344,3416 r0 top
TP8 "5010" Keystone5010 3233,2580 r0 top
TP9 "5011" Keystone5011 3233,2023 r0 top
TP10 "5011" Keystone5011 250,3250 r0 top
TP11 "5010" Keystone5010 3233,1286.32 r180 top
TP12 "5012" Keystone5012 250,900 r0 top
TP13 "5011" Keystone5011 3233.47,824 r0 top
TP14 "5012" Keystone5012 2347,1705 r0 top
TP15 "5011" Keystone5011 250,600 r0 top
TP16 "TESTPOINT" TP_25MIL-SMT 1768,2891 r90 bottom
TP17 "TESTPOINT" TP_25MIL-SMT 1768,2610 r90 bottom
TP18 "TESTPOINT" TP_25MIL-SMT 1769,1208 r90 bottom
TP19 "TESTPOINT" TP_25MIL-SMT 1769,927 r90 bottom
U1 "TPSM5D1806RDB" RDB0051A-MFG 1765,2751 r90 top
U2 "TPSM5D1806RDB" RDB0051A-MFG 1766,1068 r90 top
ZZ1 "This Assembly Note is for PCB labels only" AssemblyNoteLabel 46,6216.58 r0 top
ZZ2 "These assemblies are ESD sensitive, ESD precautions shall be observed." AssemblyNote 46,6107.7 r0 top
ZZ3 "These assemblies must be clean and free from flux and all contaminants. Use of no clean flux is not acceptable." AssemblyNote 46,6011.14 r0 top
ZZ4 "These assemblies must comply with workmanship standards IPC-A-610 Class 2, unless otherwise specified." AssemblyNote 46,5912 r0 top
ZZ5 "Place SH-J5 on J5 pins 1 and 2" AssemblyNote 46,5788 r0 top
ZZ6 "Place SH-J6 on J6 pins 3 and 4" AssemblyNote 46,5682 r0 top
ZZ7 "Place SH-J7 on J7 pins 2 and 3" AssemblyNote 46,5555 r0 top
ZZ8 "Place SH-J8 on J8 pins 1 and 2" AssemblyNote 46,5432 r0 top
ZZ9 "Place SH-J11 on J11 pins 3 and 4" AssemblyNote 46,5308 r0 top
ZZ10 "Place SH-J12 on J12 pins 3 and 4" AssemblyNote 46,5174 r0 top
ZZ11 "Place SH-J15 on J15 pins 1 and 2" AssemblyNote 46,5029 r0 top
ZZ12 "Place SH-J17 on J17 pins 2 and 3" AssemblyNote 46,4909 r0 top
ZZ13 "Place SH-J18 on J18 pins 7 and 8" AssemblyNote 46,4778 r0 top
ZZ14 "Place SH-J19 on J19 pins 3 and 4" AssemblyNote 46,4648 r0 top

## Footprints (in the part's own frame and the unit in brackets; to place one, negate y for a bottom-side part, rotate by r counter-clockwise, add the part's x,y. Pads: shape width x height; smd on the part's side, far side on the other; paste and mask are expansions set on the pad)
2SN-BK-G [mil] "Samtec STEP model"
  round 1 on Mech3: 0(0,0)
0603 [mm] "0603 from SM-752 data"
  rect 1x0.95 smd: 1(-0.8,0) 2(0.8,0)
  silkscreen extent -1.52,-0.69 1.52,0.69
1206_180 [mm] "1206_180"
  rect 1.1x1.6 smd: 1(-1.7,0) 2(1.7,0)
  silkscreen extent -0.9,-1 0.9,1
1206_190 [mm] "1206_190"
  rect 1.1x1.6 smd: 1(-1.7,0) 2(1.7,0)
  silkscreen extent -0.9,-1 0.9,1
7343-40 [mm] "Molded, 2-Leads, Body 7.3x4.3mm, Height 4mm"
  rect 2.4x2.9 smd: 1(-3.05,0) 2(3.05,0)
  silkscreen extent -3.8,-2.25 3.8,2.25
AssemblyNote [mil] "Assembly Note"
AssemblyNoteLabel [mil] "Assembly Note for PCB Labels"
CE_Mark_5mm [mil] "Minimum text height for CE Mark"
CONN_PEC03SAAN [mm] "SULLINS"
  rect 1.5x1.5 hole 1.016: 1(-2.54,0)
  round 1.5 hole 1.016: 2(0,0) 3(2.54,0)
  silkscreen extent -4.72,-1.27 3.81,1.27
CONN_PEC04DAAN [mm] "SULLINS"
  rect 1.65x1.65 hole 1.016 mask+0: 1(-3.81,-1.27)
  round 1.65 hole 1.016 mask+0: 2(-3.81,1.27) 3(-1.27,-1.27) 4(-1.27,1.27) 5(1.27,-1.27) 6(1.27,1.27) 7(3.81,-1.27) 8(3.81,1.27)
  silkscreen extent -6.18,-2.6 5.08,2.54
CONN_PEC05DAAN [mm] "SULLINS"
  rect 1.65x1.65 hole 1.016 mask+0: 1(-5.08,-1.27)
  round 1.65 hole 1.016 mask+0: 2(-5.08,1.27) 3(-2.54,-1.27) 4(-2.54,1.27) 5(0,-1.27) 6(0,1.27) 7(2.54,-1.27) 8(2.54,1.27) 9(5.08,-1.27) 10(5.08,1.27)
  silkscreen extent -7.45,-2.6 6.35,2.54
FCC_disclaimer [mil]
Fiducial10-30 [mm]
  round 1 smd mask+0: 1(0,0)
  Top Layer keep-out circle w1.678: c0,0 r0.75
Keystone5010 [mil] "Keystone Multipurpose loops"
  round 87 hole 63: 1(0,0)
  silkscreen extent -70,-70 70,70
Keystone5011 [mil] "Keystone Multipurpose loops"
  round 87 hole 63: 1(0,0)
  silkscreen extent -70,-70 70,70
Keystone5012 [mil] "Keystone Multipurpose loops"
  round 87 hole 63: 1(0,0)
  silkscreen extent -70,-70 70,70
Mill-max_310-43-102-41-001000 [mm] "Mill-max"
  rect 1.35x1.35 hole 0.75: 1(-1.27,0)
  round 1.35 hole 0.75: 2(1.27,0)
  silkscreen extent -3.22,-1.3 2.6,1.3
Net-Tie_10mil#1 [mil] "10mil net tie, no solder mask opening, no solder paste"
  rect 10x10 smd paste-5 mask+0: 1(-10,0) 2(10,0)
Net-Tie_10mil#2 [mil] "10mil net tie, no solder mask opening, no solder paste"
  rect 10x10 on Mid3 paste-5 mask+0: 1(-10,0) 2(10,0)
On-Shore_ED120_2DS [mm] "ONSHORE"
  rrect5% 2x2 hole 1.25: 1(-2.54,0)
  round 2 hole 1.25: 2(2.54,0)
  silkscreen extent -5.6,-4 5.12,5
RDB0051A-MFG [mm]
  round 0.256 smd paste-1000 mask+0: 1(-2.267,3.562) 15(-2.267,-3.562)
  rrect40% 0.7x0.25 smd paste+0 mask+0: 2(-2.6,3) 3(-2.6,2.5) 7(-2.6,0.5) 8(-2.6,0) 9(-2.6,-0.5) 13(-2.6,-2.5) 14(-2.6,-3) 25(2.6,-3) 26(2.6,-2.5) 30(2.6,-0.5) 31(2.6,0) 32(2.6,0.5) 36(2.6,2.5) 37(2.6,3)
  rrect40% 1.2x0.25 smd paste+0 mask+0: 4(-2.35,2) 5(-2.35,1.5) 6(-2.35,1) 10(-2.35,-1) 11(-2.35,-1.5) 12(-2.35,-2) 27(2.35,-2) 28(2.35,-1.5) 29(2.35,-1) 33(2.35,1) 34(2.35,1.5) 35(2.35,2)
  rrect40% 0.25x0.7 smd paste+0 mask+0: 16(-1.75,-3.85) 17(-1.25,-3.85) 18(-0.75,-3.85) 19(-0.25,-3.85) 20(0.25,-3.85) 21(0.75,-3.85) 22(1.25,-3.85) 23(1.75,-3.85) 39(1.75,3.85) 40(1.25,3.85) 41(0.75,3.85) 42(0.25,3.85) 43(-0.25,3.85) 44(-0.75,3.85) 45(-1.25,3.85) 46(-1.75,3.85)
  round 0.324 smd paste-1000 mask+0: 24(2.312,-3.562) 38(2.312,3.562)
  rrect4% 2.5x5 smd paste-1000 mask+0: 47-48-49-50-51(0,0)
  silkscreen extent -3.65,-4.3 2.8,4.3
SM_RADIAL_G [mm] "10 x 10.2mm:  Panasonic G"
  rect 4.1x2 smd: 1(-4.35,0) 2(4.35,0)
  silkscreen extent -5.35,-5.35 5.35,5.35
TI_Stacked_Overlay_Small [mil]
TP_25MIL-SMT [mil]
  round 25 smd mask+0: 1(0,0)
WEEE_Minimum [mil] "WEEElie bin"
  silkscreen extent 22,-71 54,74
